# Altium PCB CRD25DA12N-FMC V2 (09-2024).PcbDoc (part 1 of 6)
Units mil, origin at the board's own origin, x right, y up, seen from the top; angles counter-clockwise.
Board outline 8000 x 8000 mil, 6 copper layers (Top Layer, Layer 2, Layer 3, Layer 4, Layer 5, Bottom Layer), stack 91 mil thick; 602 components, 333 nets, 1670 pads, 639 vias.
Unrouted connection lines stored in the file: 1.
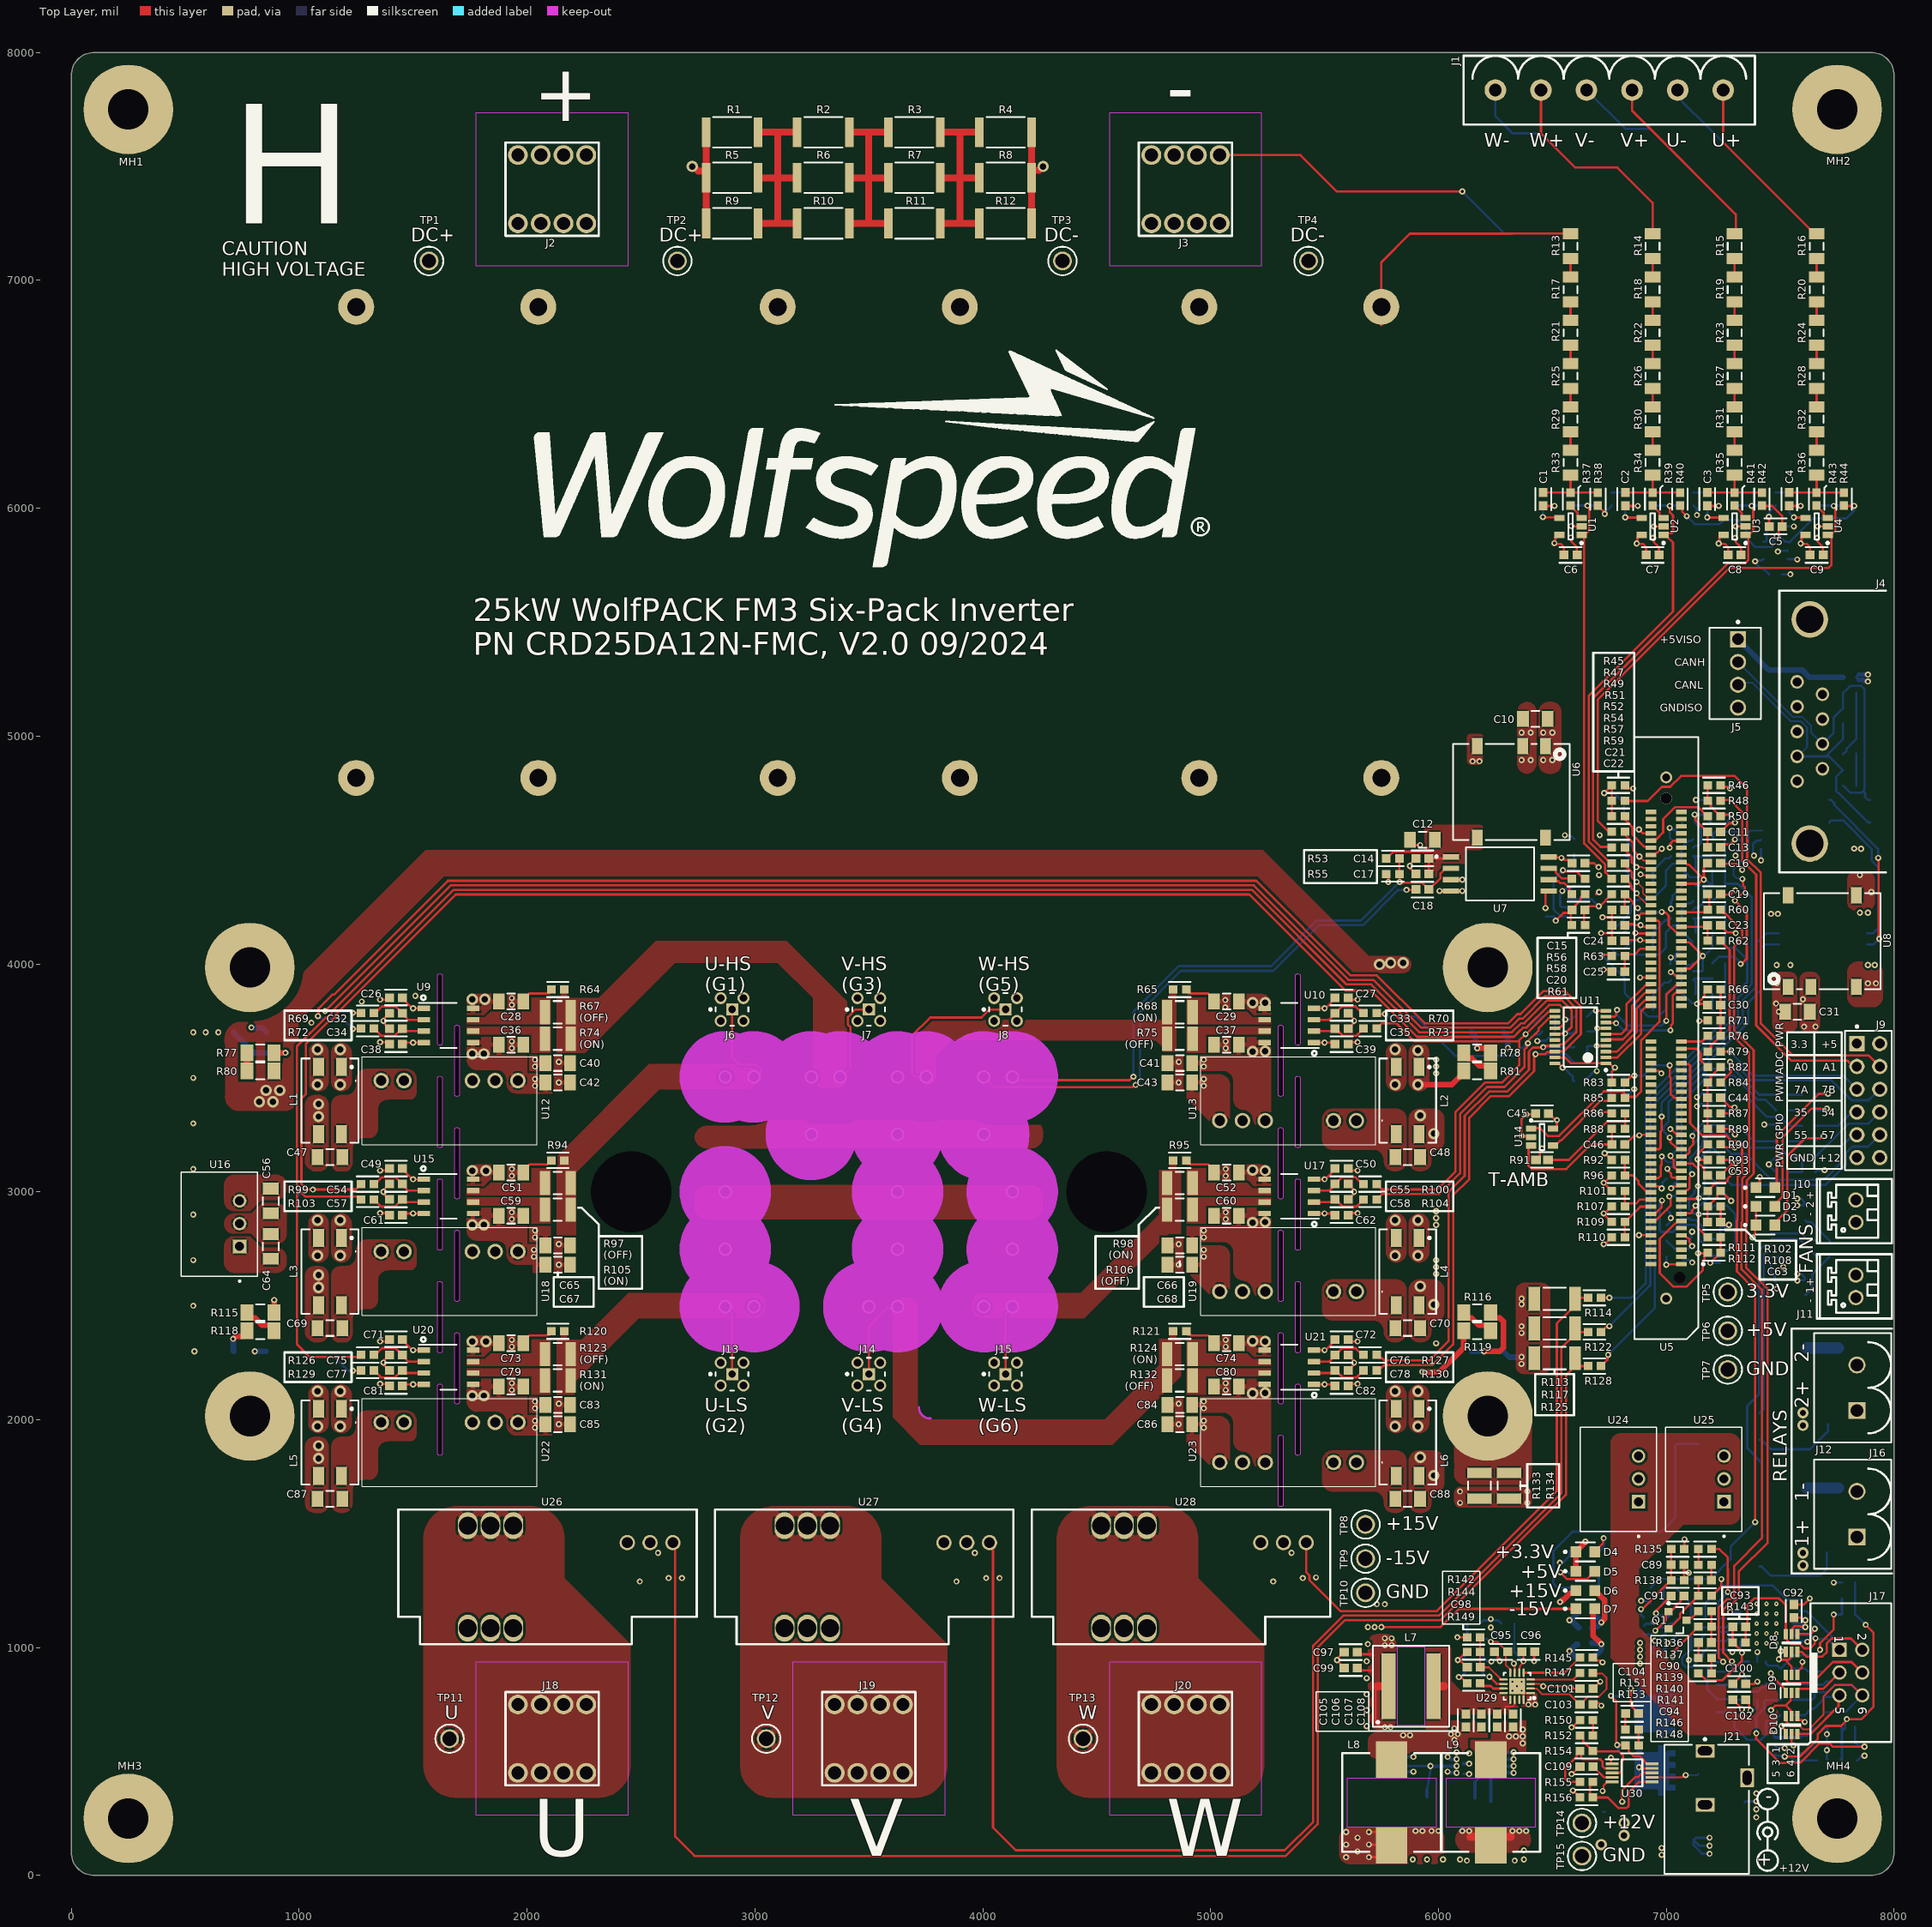
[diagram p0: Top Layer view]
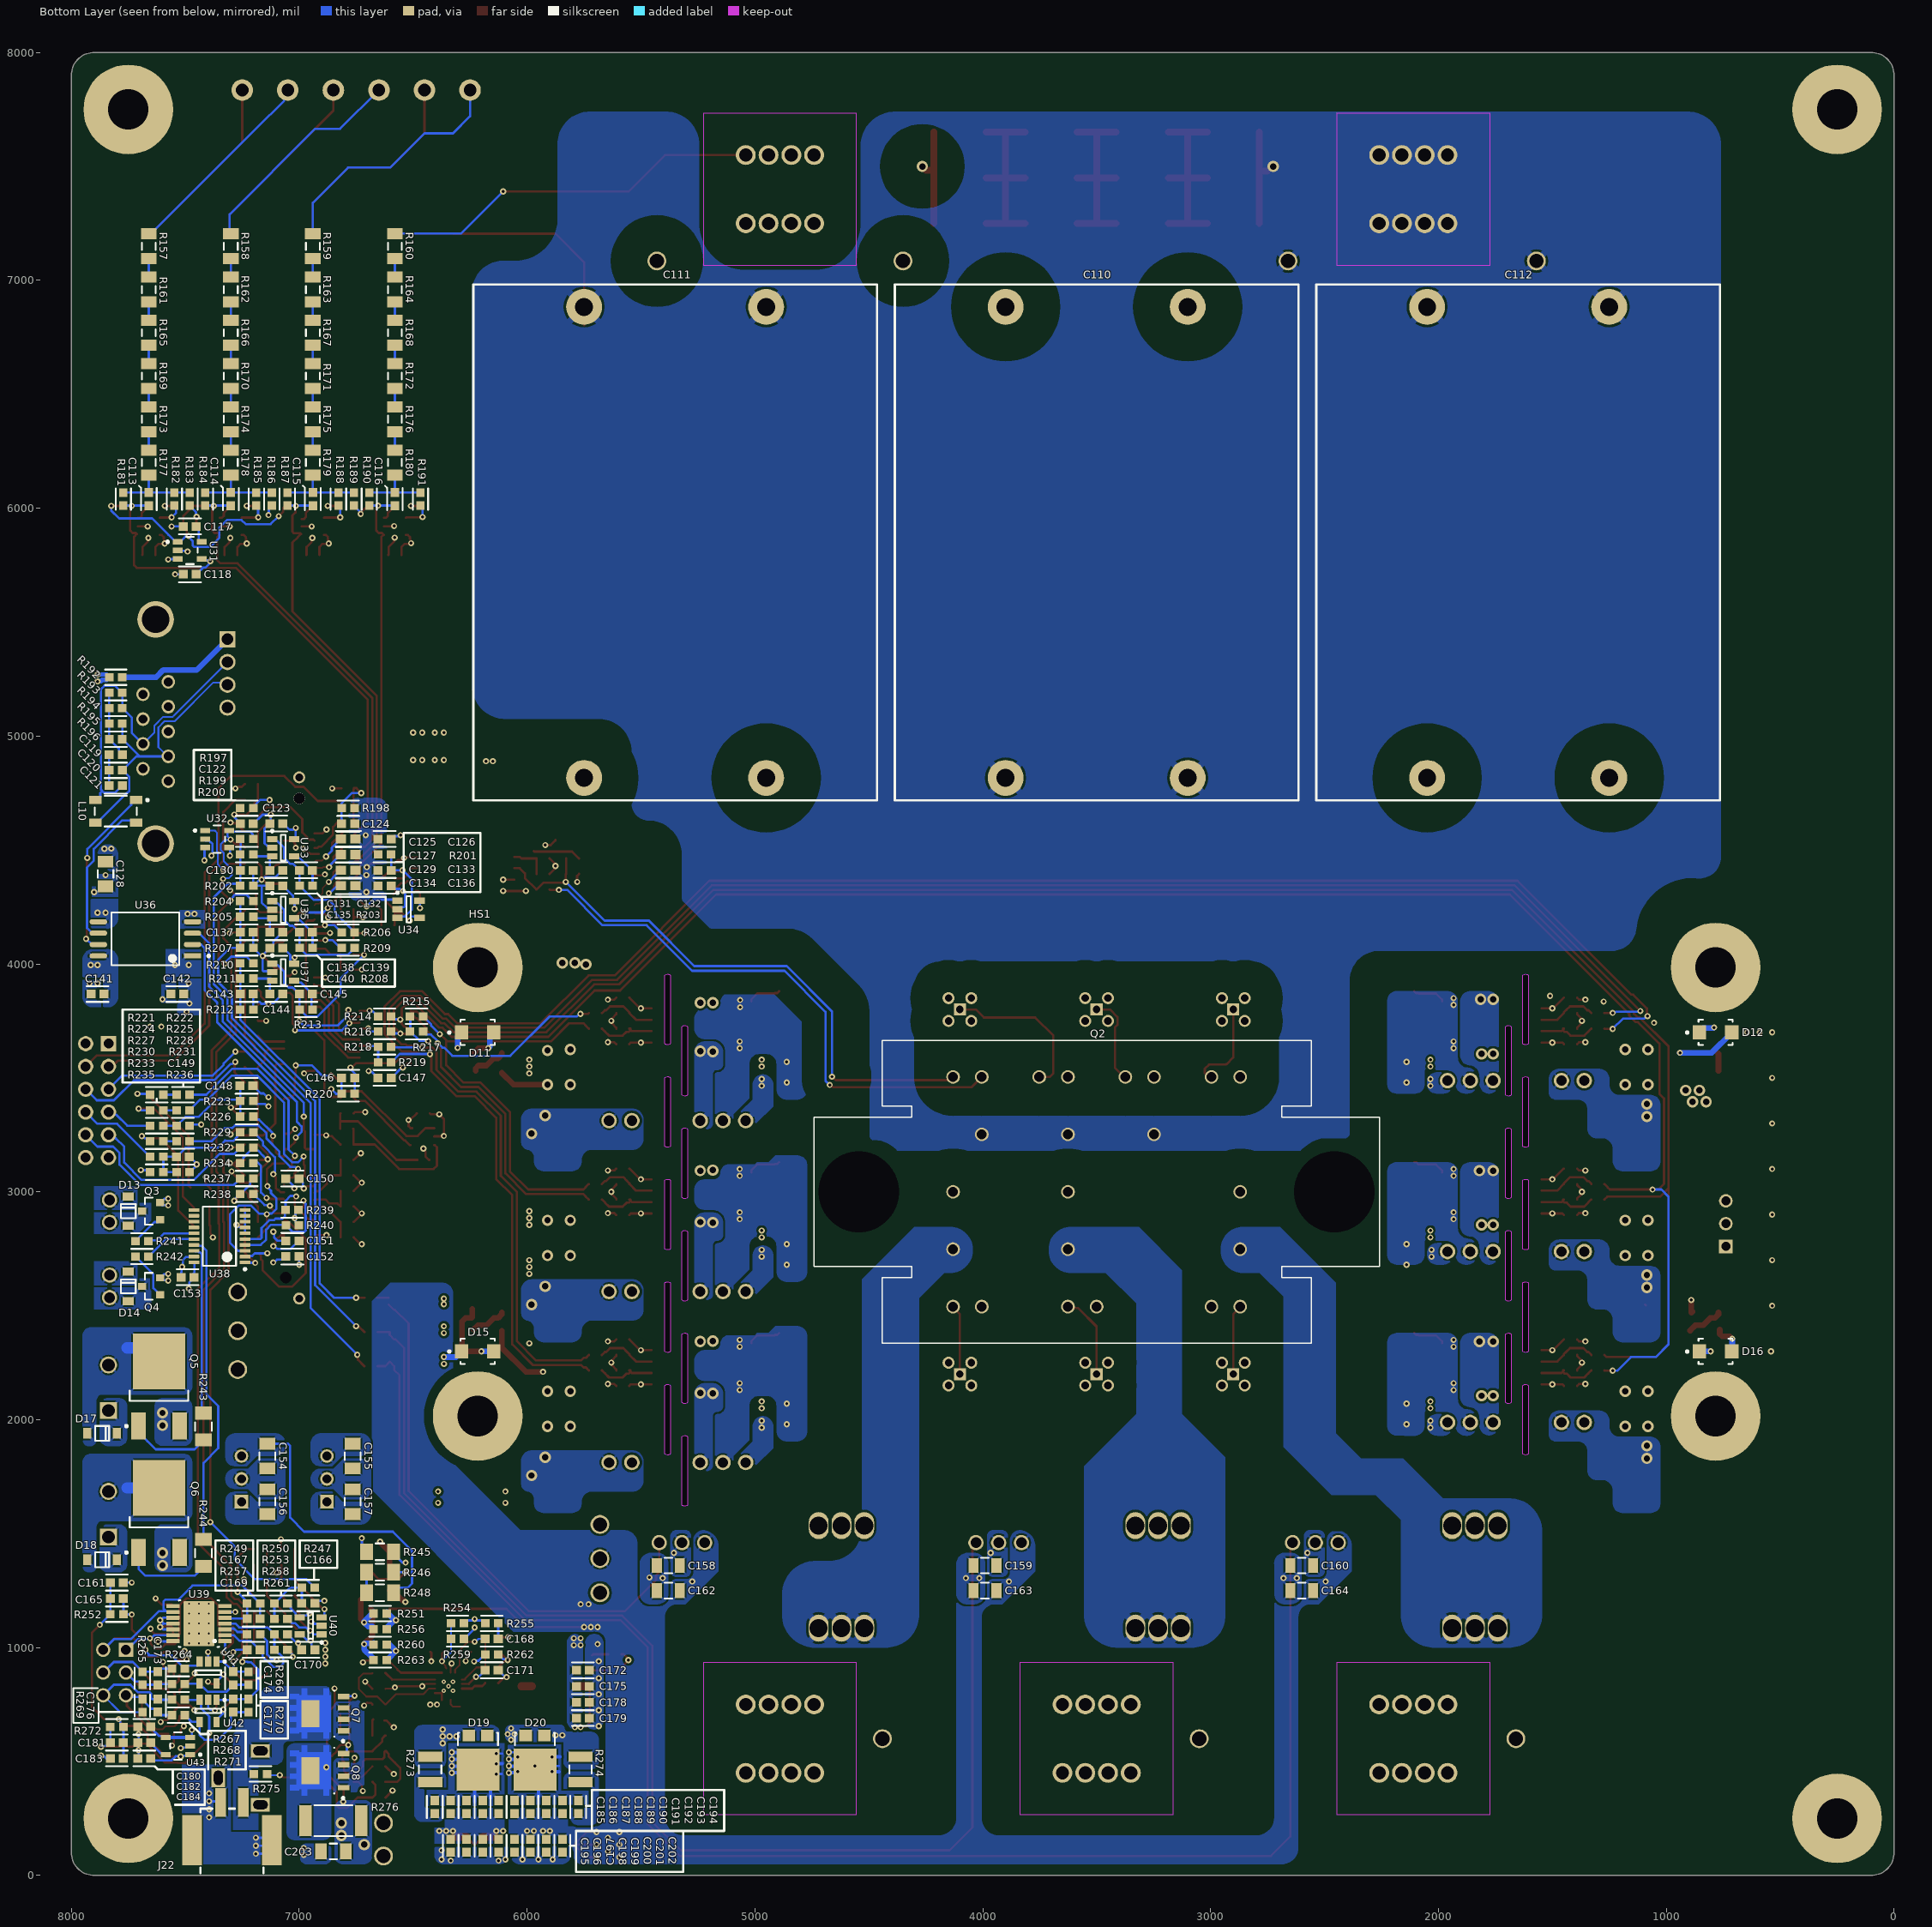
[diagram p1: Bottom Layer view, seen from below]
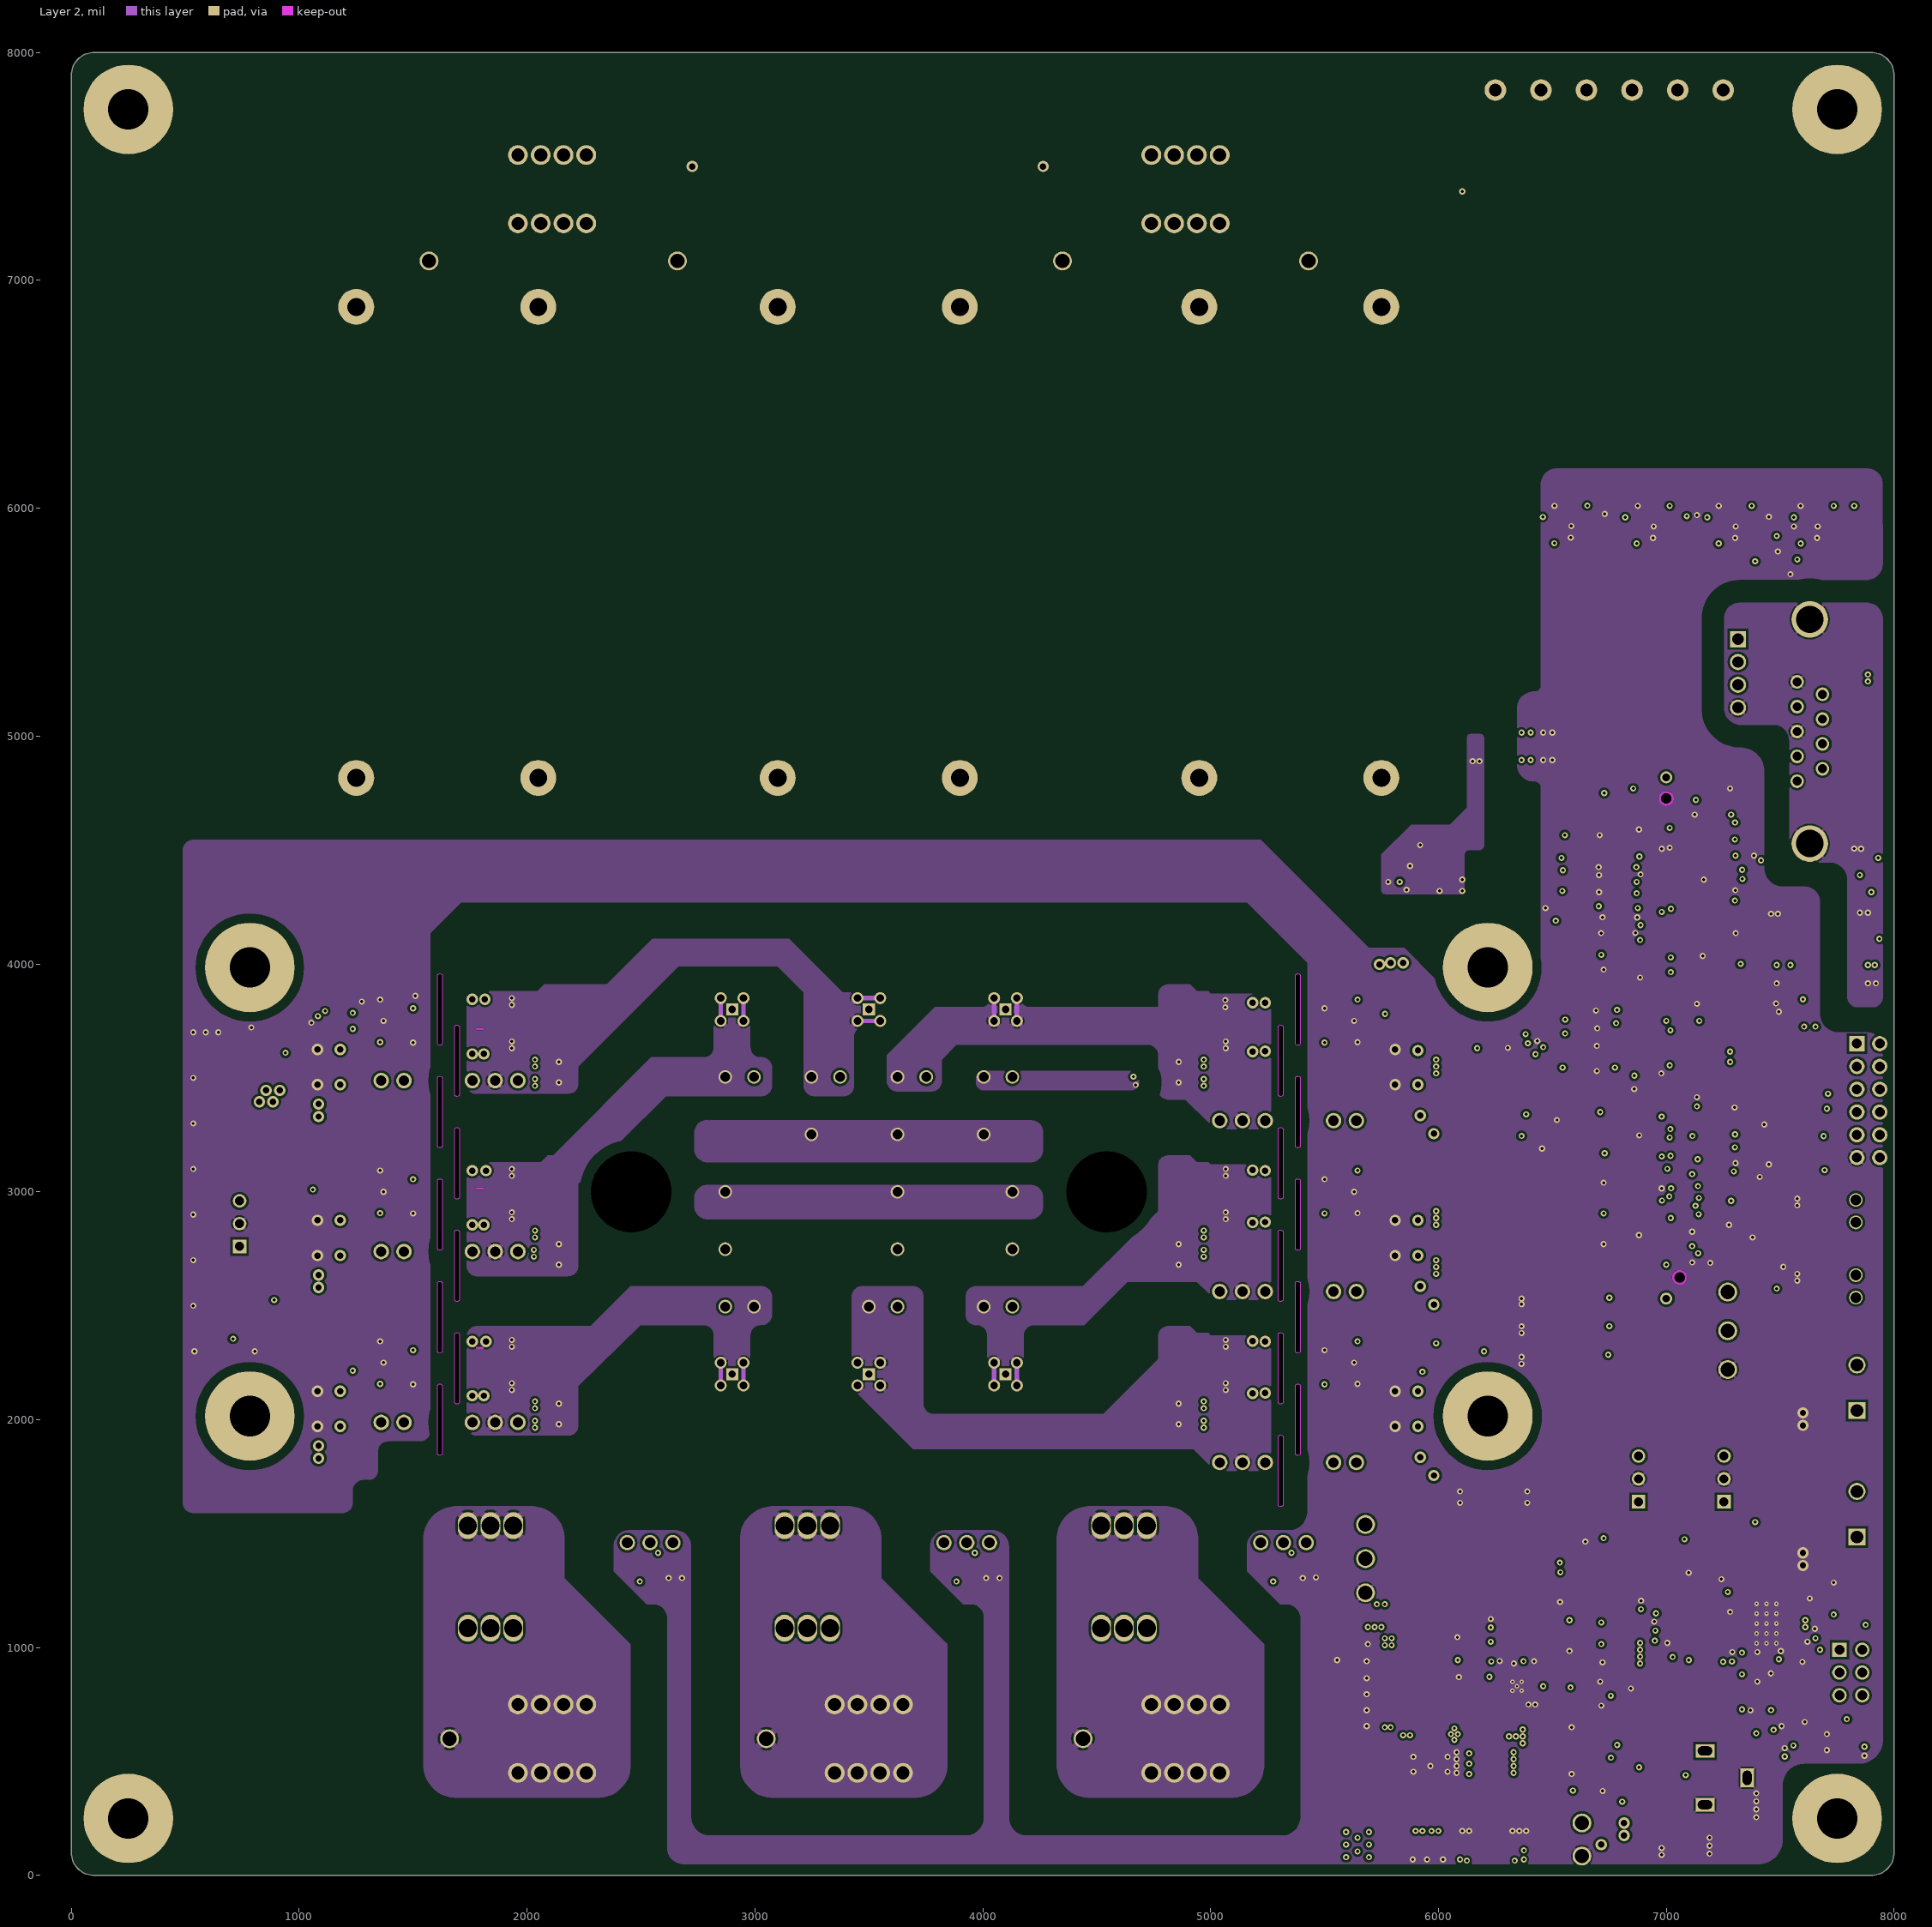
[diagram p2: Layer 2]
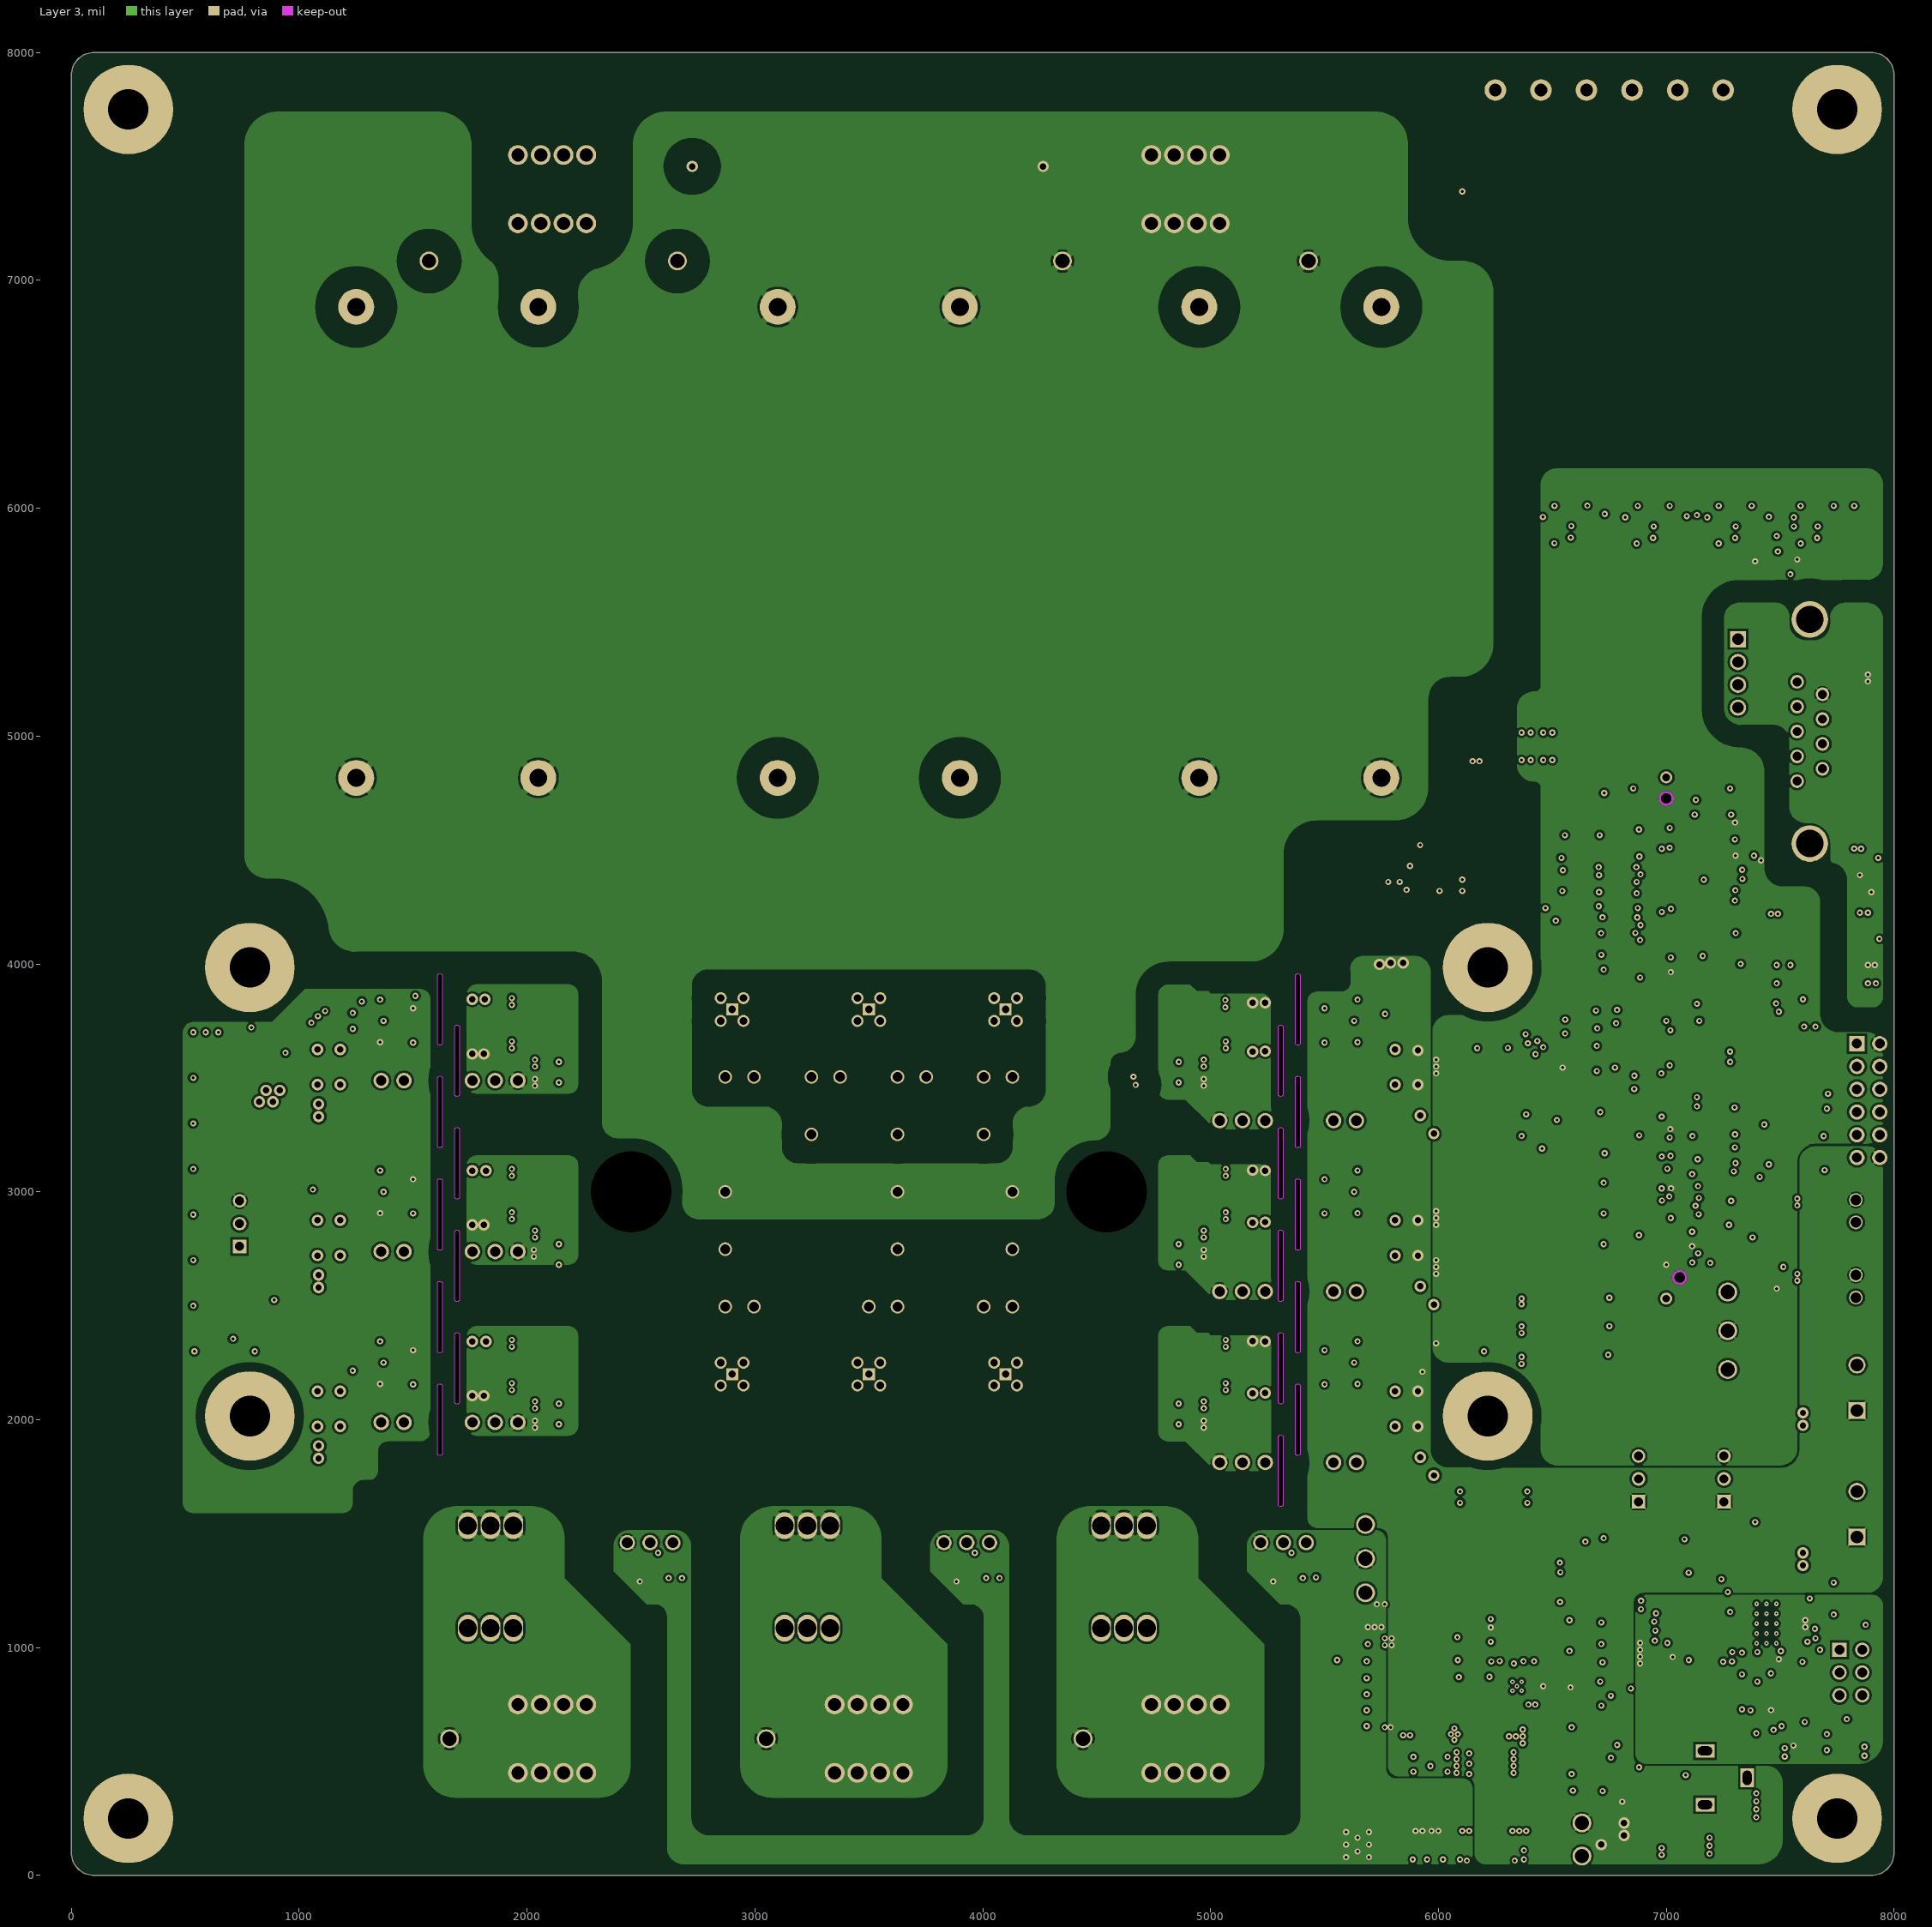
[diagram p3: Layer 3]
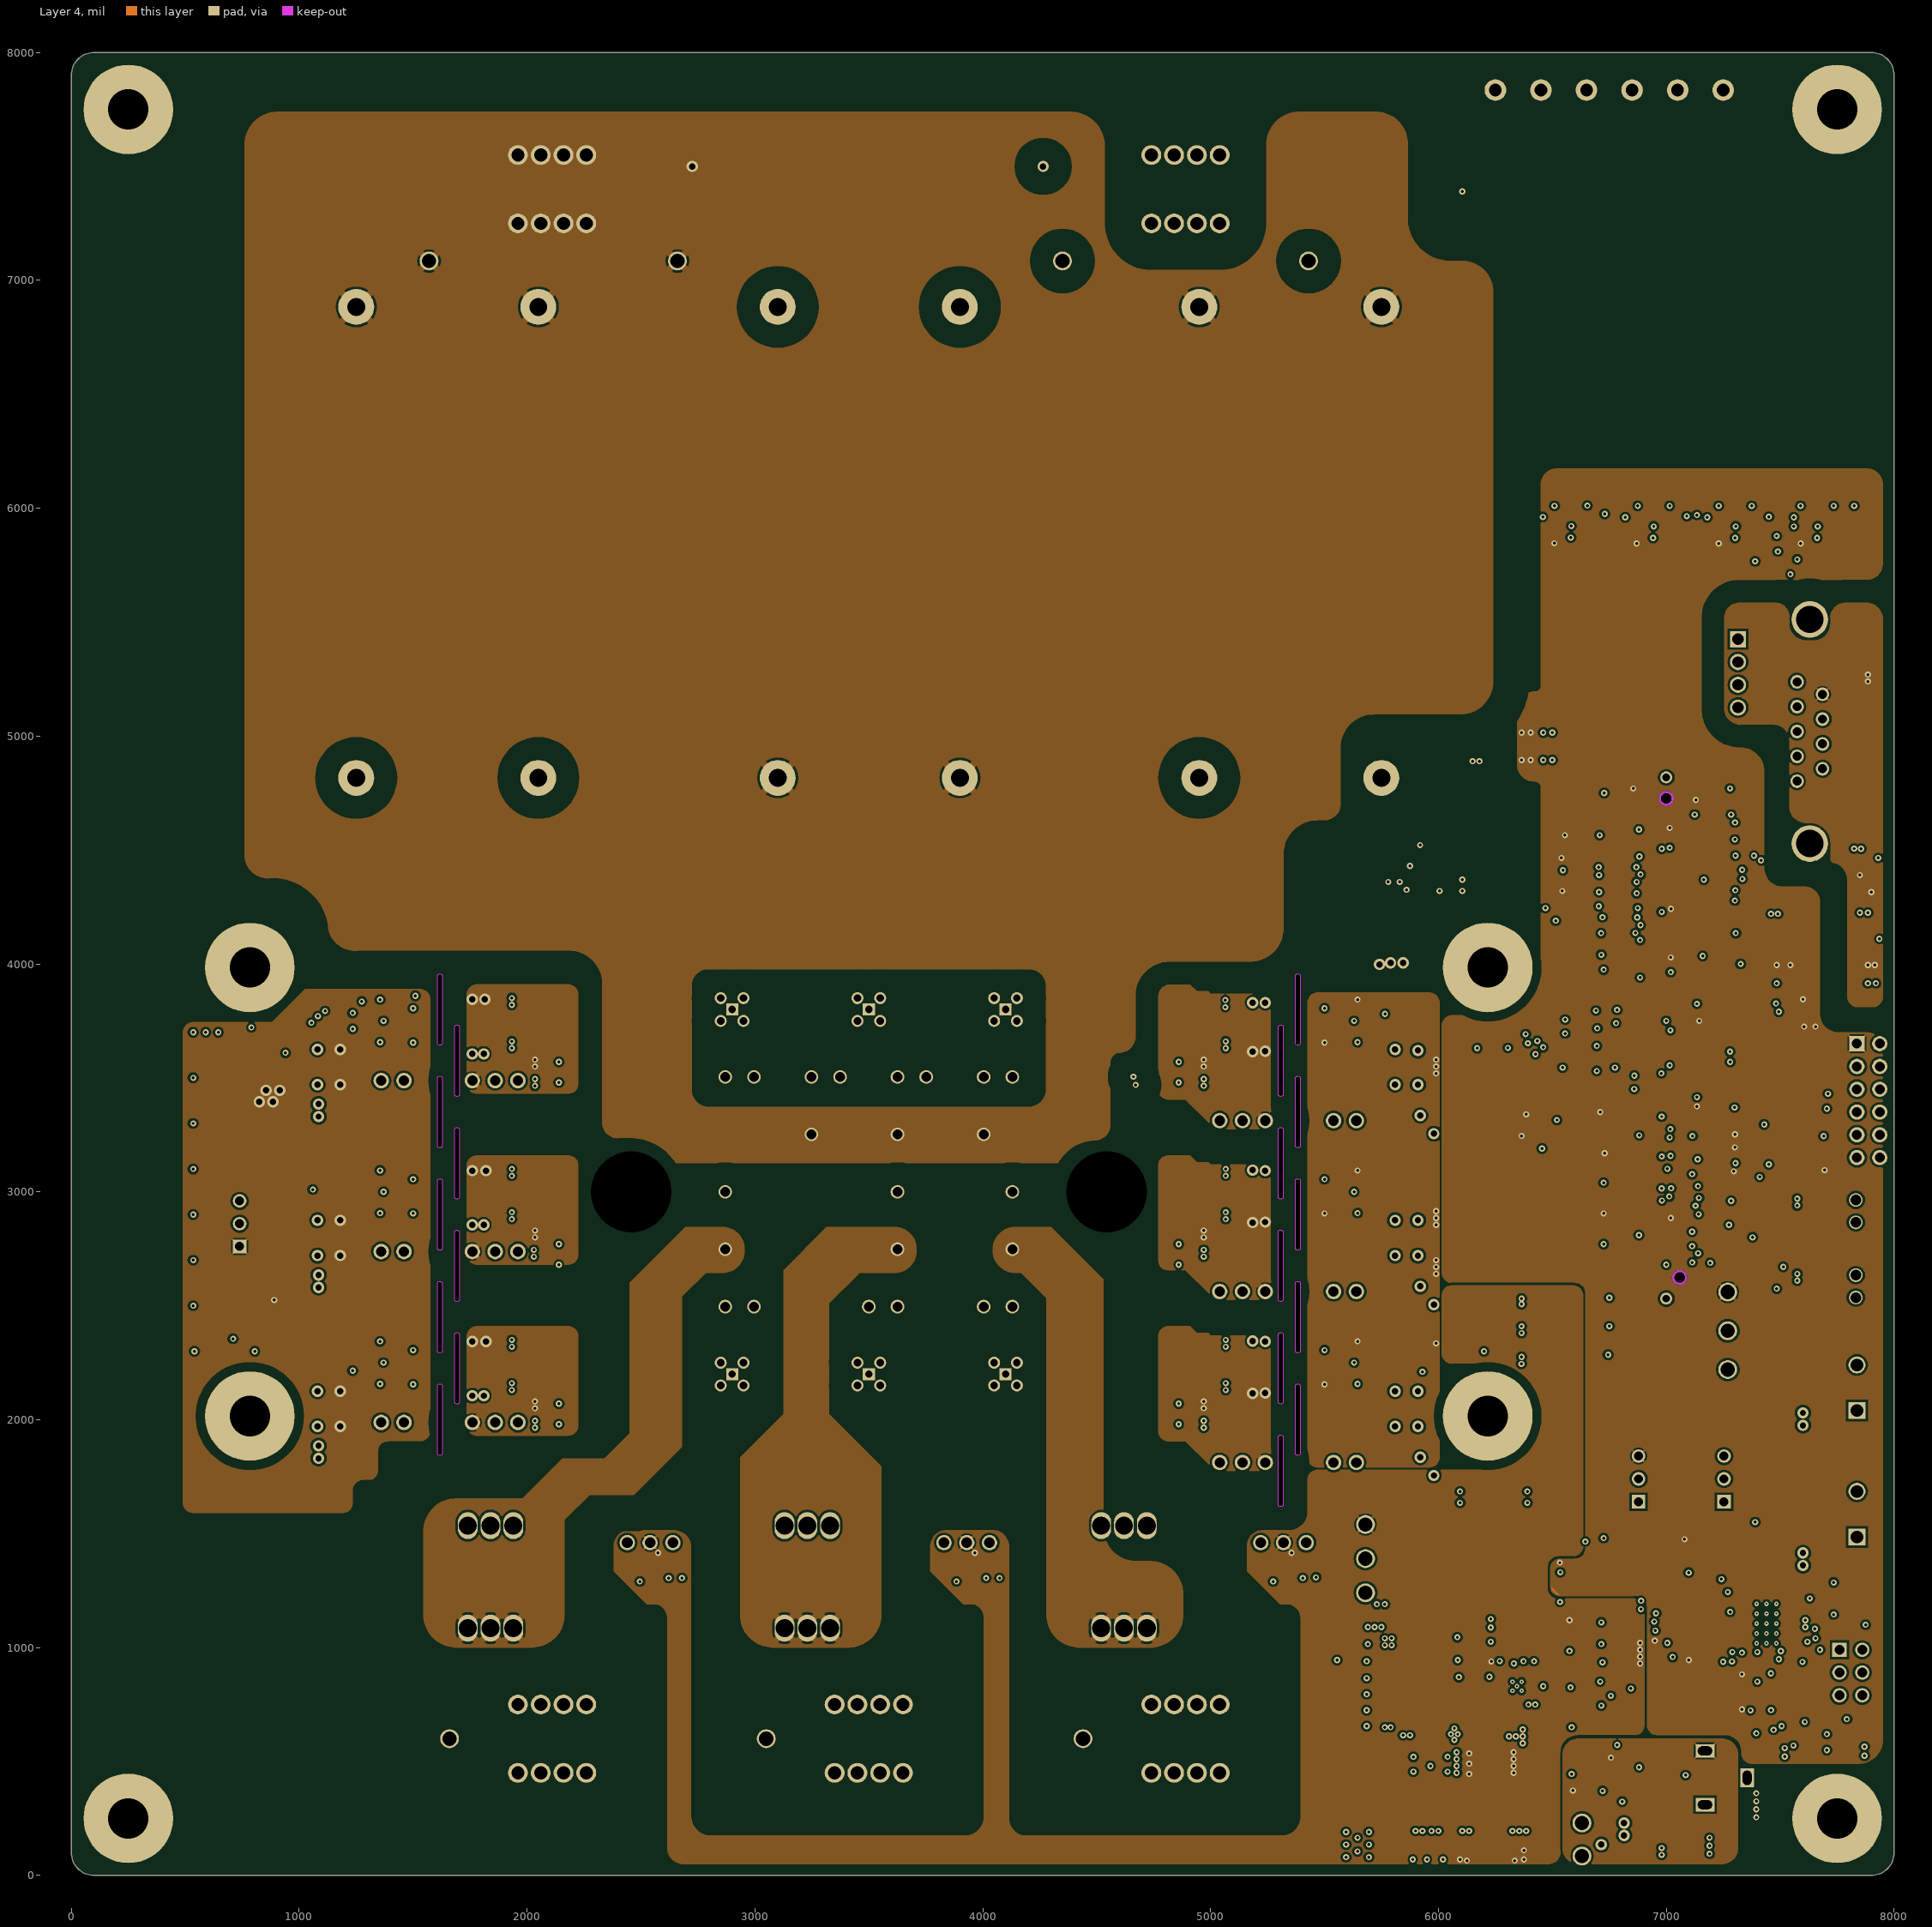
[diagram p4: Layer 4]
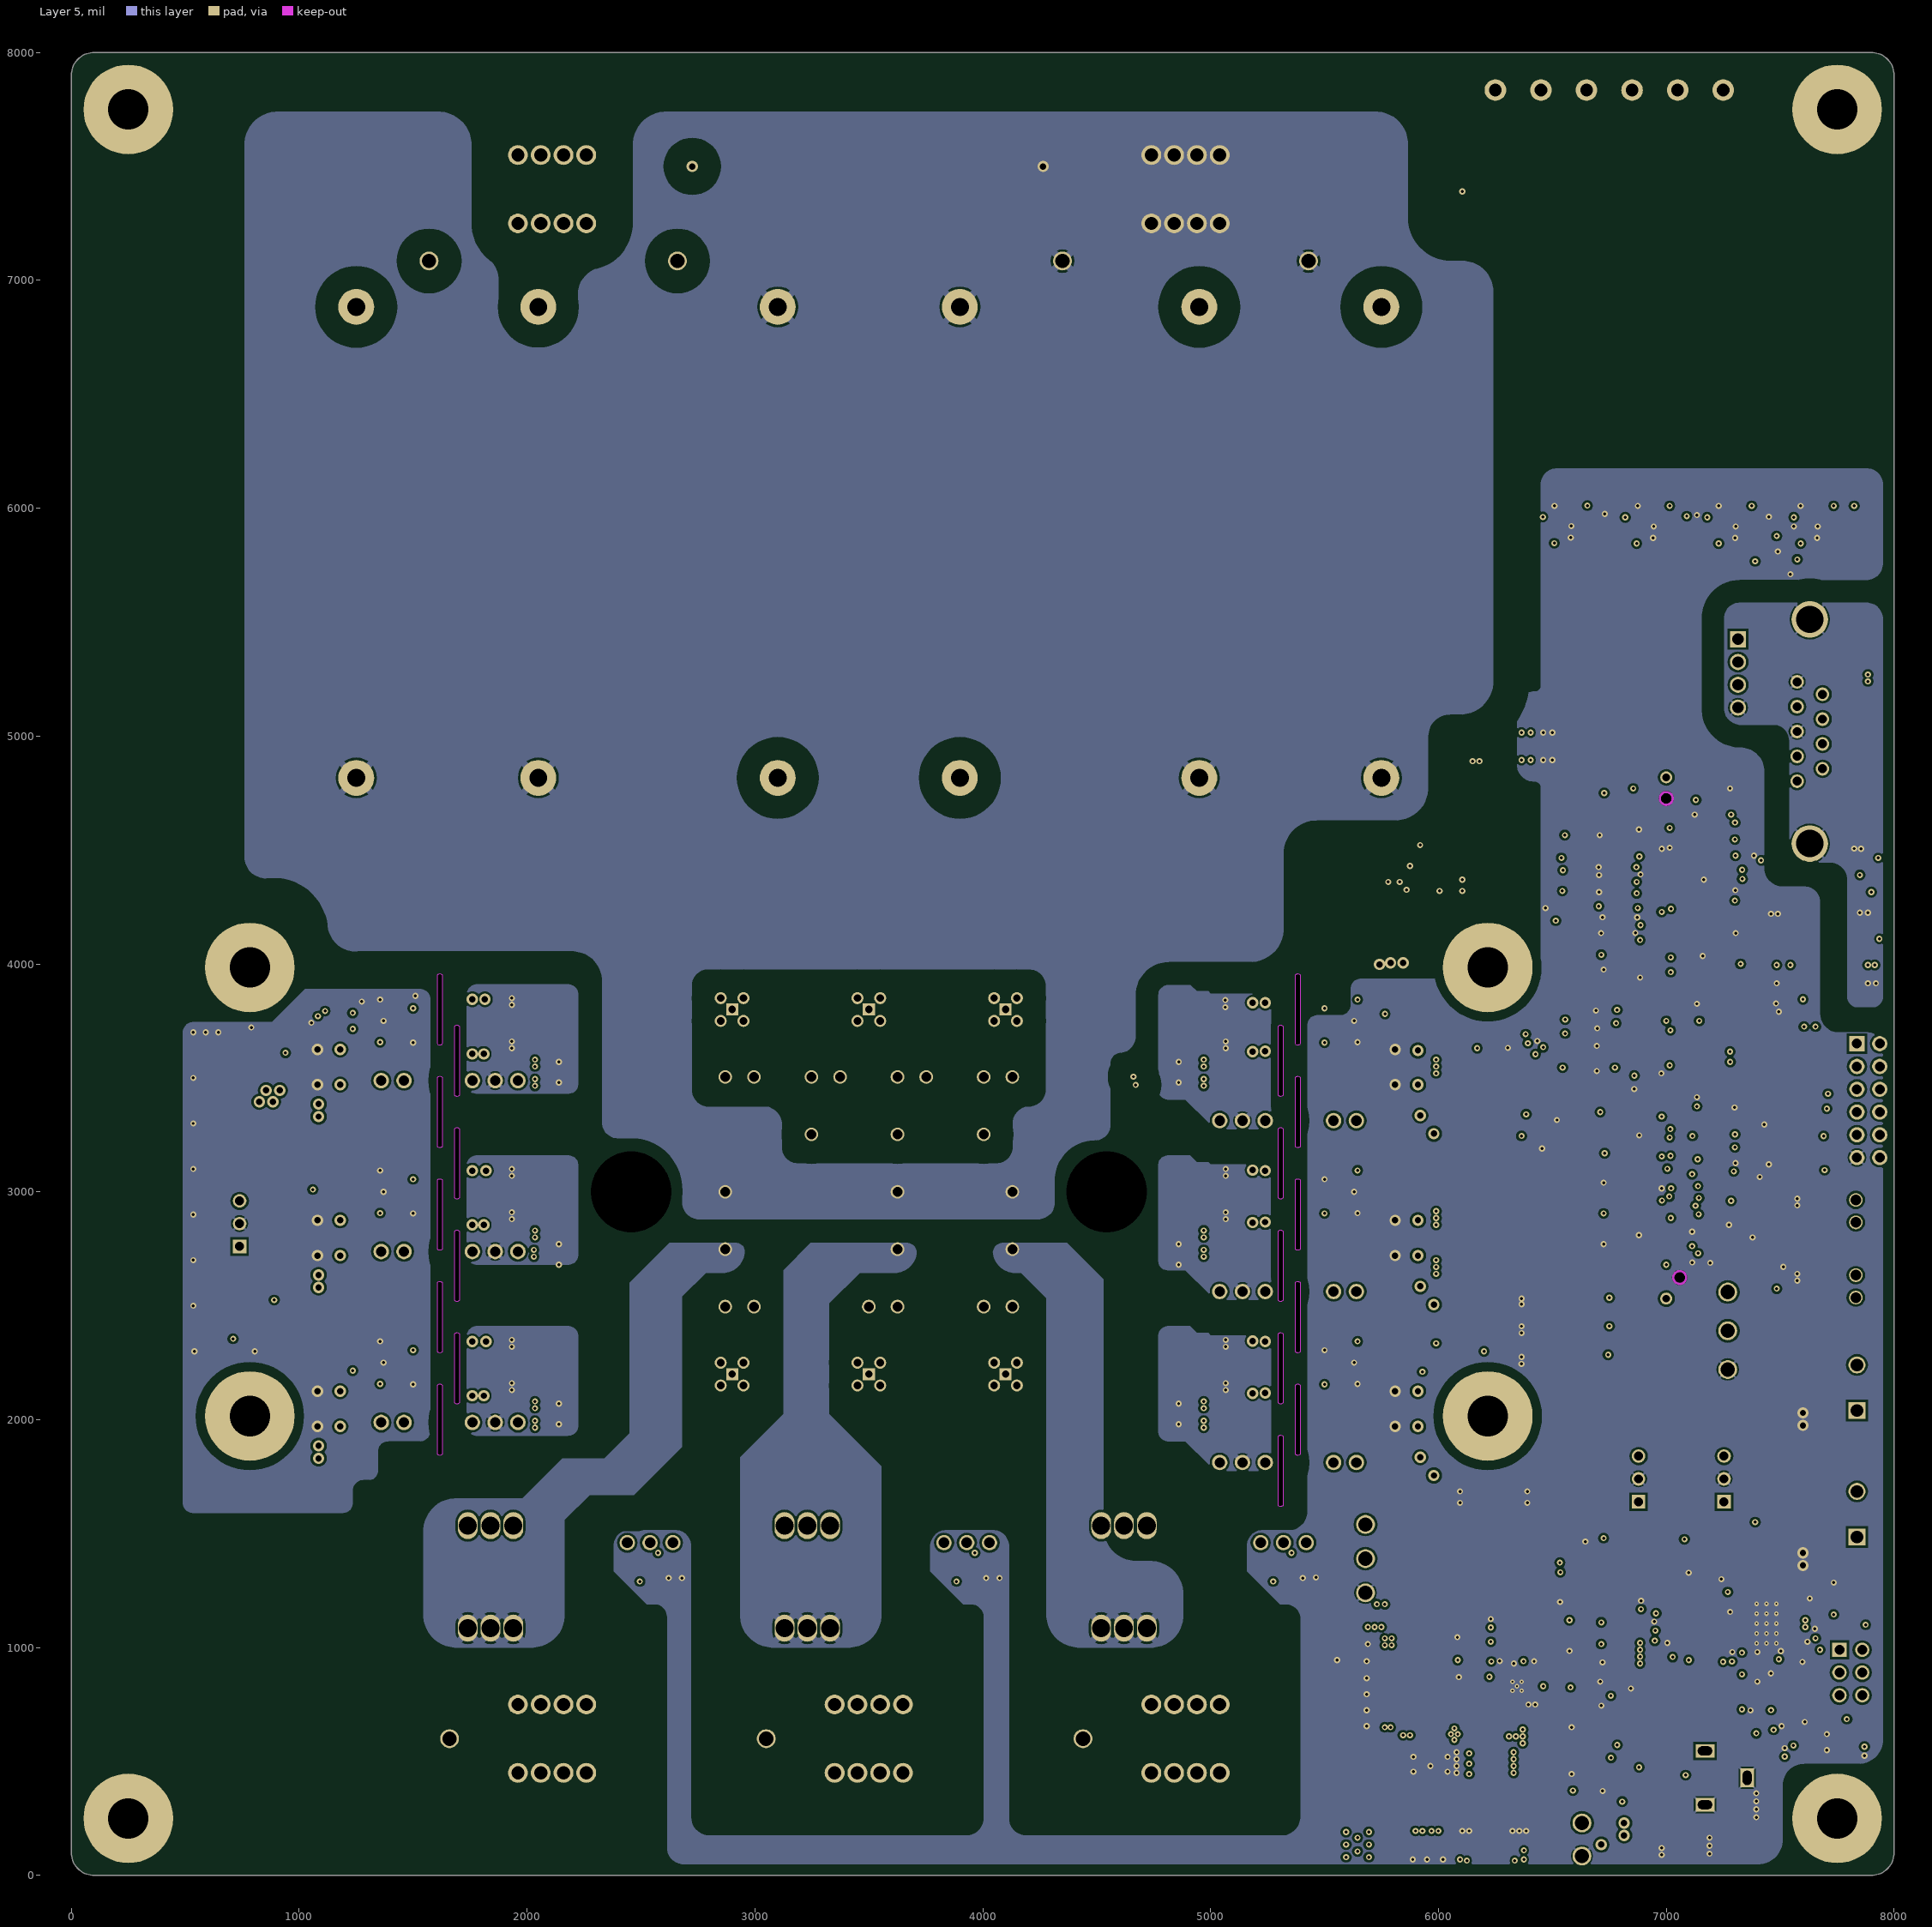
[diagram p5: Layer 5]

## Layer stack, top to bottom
Top Solder: solder mask 1, SM-002, Dk 4
Top Layer: signal copper 2.756
Dielectric 2: prepreg 7.894, PP-006, Dk 4.1
Layer 2: signal copper 2.756
Dielectric 4: prepreg 7.894, PP-006, Dk 4.1
Layer 3: signal copper 2.756
Dielectric 1: dielectric 42.888, FR-4, Dk 4.8
Layer 4: signal copper 2.756
Dielectric 5: prepreg 7.894, PP-006, Dk 4.1
Layer 5: signal copper 2.756
Dielectric 3: prepreg 7.894, PP-006, Dk 4.1
Bottom Layer: signal copper 2.756
Bottom Solder: solder mask 1, SM-002, Dk 4

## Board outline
0,100 0,7900 cw(c100,7900) 100,8000 7900,8000 cw(c7900,7900) 8000,7900 8000,100 cw(c7900,100) 7900,0 100,0 cw(c100,100)
cut-out: 5370,3950 5370,3650 ccw(c5382.5,3662.5) 5395,3650 5395,3950 ccw(c5382.5,3937.5)
cut-out: 5295,3725 5295,3425 ccw(c5307.5,3437.5) 5320,3425 5320,3725 ccw(c5307.5,3712.5)
cut-out: 5370,3500 5370,3200 ccw(c5382.5,3212.5) 5395,3200 5395,3500 ccw(c5382.5,3487.5)
cut-out: 5295,3275 5295,2975 ccw(c5307.5,2987.5) 5320,2975 5320,3275 ccw(c5307.5,3262.5)
cut-out: 5370,3050 5370,2750 ccw(c5382.5,2762.5) 5395,2750 5395,3050 ccw(c5382.5,3037.5)
cut-out: 5295,2825 5295,2525 ccw(c5307.5,2537.5) 5320,2525 5320,2825 ccw(c5307.5,2812.5)
cut-out: 5370,2600 5370,2300 ccw(c5382.5,2312.5) 5395,2300 5395,2600 ccw(c5382.5,2587.5)
cut-out: 5295,2375 5295,2075 ccw(c5307.5,2087.5) 5320,2075 5320,2375 ccw(c5307.5,2362.5)
cut-out: 5370,2150 5370,1850 ccw(c5382.5,1862.5) 5395,1850 5395,2150 ccw(c5382.5,2137.5)
cut-out: 5295,1925 5295,1625 ccw(c5307.5,1637.5) 5320,1625 5320,1925 ccw(c5307.5,1912.5)
cut-out: 1605,2150 1605,1850 ccw(c1617.5,1862.5) 1630,1850 1630,2150 ccw(c1617.5,2137.5)
cut-out: 1680,2375 1680,2075 ccw(c1692.5,2087.5) 1705,2075 1705,2375 ccw(c1692.5,2362.5)
cut-out: 1605,2600 1605,2300 ccw(c1617.5,2312.5) 1630,2300 1630,2600 ccw(c1617.5,2587.5)
cut-out: 1680,2825 1680,2525 ccw(c1692.5,2537.5) 1705,2525 1705,2825 ccw(c1692.5,2812.5)
cut-out: 1605,3050 1605,2750 ccw(c1617.5,2762.5) 1630,2750 1630,3050 ccw(c1617.5,3037.5)
cut-out: 1680,3275 1680,2975 ccw(c1692.5,2987.5) 1705,2975 1705,3275 ccw(c1692.5,3262.5)
cut-out: 1605,3500 1605,3200 ccw(c1617.5,3212.5) 1630,3200 1630,3500 ccw(c1617.5,3487.5)
cut-out: 1680,3725 1680,3425 ccw(c1692.5,3437.5) 1705,3425 1705,3725 ccw(c1692.5,3712.5)
cut-out: 1605,3950 1605,3650 ccw(c1617.5,3662.5) 1630,3650 1630,3950 ccw(c1617.5,3937.5)

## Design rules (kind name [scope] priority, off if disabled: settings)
Clearance Keepout [IsKeepOut] p1: gap=0 ignorepadtopadclearanceinfootprint=FALSE
Clearance DC+/-_Heatsink [InNet('DC-') Or InNet('DC+') vs HasFootprint('LA 6 150 12')] p2: gap=160 ignorepadtopadclearanceinfootprint=FALSE except(0: Arc-Hole Track-Hole SMDPad-Hole THPad-Hole Via-Hole Fill-Hole Poly-Hole Region-Hole Text-Hole)
Clearance NTC_Heatsink [InNetClass('NTC Class') vs HasFootprint('LA 6 150 12')] p3: gap=120 ignorepadtopadclearanceinfootprint=FALSE except(0: Arc-Hole Track-Hole SMDPad-Hole THPad-Hole Via-Hole Fill-Hole Poly-Hole Region-Hole Text-Hole)
Clearance Heatsink [All vs HasFootprint('LA 6 150 12')] p4: gap=40 ignorepadtopadclearanceinfootprint=FALSE except(0: Arc-Hole Track-Hole SMDPad-Hole THPad-Hole Via-Hole Fill-Hole Poly-Hole Region-Hole Text-Hole)
Clearance Module_Mount [All vs HoleDiameter = 354.331] p5: gap=50 ignorepadtopadclearanceinfootprint=FALSE
Clearance Cutout [IsBoardCutoutRegion] p6: gap=20 ignorepadtopadclearanceinfootprint=TRUE except(0: Arc-Hole Track-Hole SMDPad-Hole THPad-Hole Via-Hole Fill-Hole Poly-Hole Region-Hole Text-Hole)
Clearance LV_to_G [InNetClass('LV Pours') vs InNetClass('Gate Class')] p7: gap=160 ignorepadtopadclearanceinfootprint=FALSE except(0: Arc-Hole Track-Hole SMDPad-Hole THPad-Hole Via-Hole Fill-Hole Poly-Hole Region-Hole Text-Hole)
Clearance DC+/-_to_LV [InNet('DC-') OR InNet('DC+') OR InNetClass('U Class') OR InNetClass('V Class') OR InNetClass('W Class') vs InNetClass('LV Pours')] p8: gap=160 ignorepadtopadclearanceinfootprint=FALSE except(0: Arc-Hole Track-Hole SMDPad-Hole THPad-Hole Via-Hole Fill-Hole Poly-Hole Region-Hole Text-Hole)
Clearance DC+_Internal [(InNet('DC-') Or InNetClass('DC+ Class')) AND InLayerClass('Internal Layers')] p9: gap=100 ignorepadtopadclearanceinfootprint=FALSE except(0: Arc-Hole Track-Hole SMDPad-Hole THPad-Hole Via-Hole Fill-Hole Poly-Hole Region-Hole Text-Hole)
Clearance DC+_Pins_External [InNet('DC+') AND InLayerClass('External Layers') vs (HasFootprint('FM3_SIX-PACK_3PHASE_CRW') OR HasFootprint('FP-73415-1471-MFG')) AND (InNetClass('Gate Class') OR InNetClass('NTC Class'))] p10: gap=140 ignorepadtopadclearanceinfootprint=FALSE except(0: Arc-Hole Track-Hole SMDPad-Hole THPad-Hole Via-Hole Fill-Hole Poly-Hole Region-Hole Text-Hole)
Clearance DC+_to_DC+ [InNetClass('DC+ Class') vs InNetClass('DC+ Class')] p11: gap=10 ignorepadtopadclearanceinfootprint=FALSE except(0: Arc-Hole Track-Hole SMDPad-Hole THPad-Hole Via-Hole Fill-Hole Poly-Hole Region-Hole Text-Hole)
Clearance DC+_External [InNet('DC+') AND InLayerClass('External Layers')] p12: gap=160 ignorepadtopadclearanceinfootprint=FALSE except(0: Arc-Text Arc-Hole Track-Text Track-Hole SMDPad-Text SMDPad-Hole THPad-Text THPad-Hole Via-Text Via-Hole Fill-Text Fill-Hole Poly-Text Poly-Hole Region-Text Region-Hole Text-Text Text-Hole)
Clearance CAN [InNetClass('CAN Class') vs Not InNetClass('CAN Class') And Not IsPad] p13: gap=100 ignorepadtopadclearanceinfootprint=FALSE except(0: Arc-Hole Track-Hole SMDPad-Hole THPad-Hole Via-Hole Fill-Hole Poly-Hole Region-Hole Text-Hole)
Clearance U [InNetClass('U Class') vs NOT InNetClass('U Class')] p14: gap=100 ignorepadtopadclearanceinfootprint=FALSE except(0: Arc-Text Arc-Hole Track-Text Track-Hole SMDPad-Text SMDPad-Hole THPad-Text THPad-Hole Via-Text Via-Hole Fill-Text Fill-Hole Poly-Text Poly-Hole Region-Text Region-Hole Text-Text Text-Hole)
Clearance V [InNetClass('V Class') vs NOT InNetClass('V Class')] p15: gap=100 ignorepadtopadclearanceinfootprint=FALSE except(0: Arc-Text Arc-Hole Track-Text Track-Hole SMDPad-Text SMDPad-Hole THPad-Text THPad-Hole Via-Text Via-Hole Fill-Text Fill-Hole Poly-Text Poly-Hole Region-Text Region-Hole Text-Text Text-Hole)
Clearance W [InNetClass('W Class') vs NOT InNetClass('W Class')] p16: gap=100 ignorepadtopadclearanceinfootprint=FALSE except(0: Arc-Hole Track-Hole SMDPad-Hole THPad-Hole Via-Hole Fill-Hole Poly-Hole Region-Hole Text-Text Text-Hole)
Clearance NTC_External [InNetClass('NTC Class') AND InLayerClass('External Layers') vs NOT InNetClass('NTC Class') AND NOT IsPad] p17: gap=150 ignorepadtopadclearanceinfootprint=FALSE except(0: Arc-Hole Track-Hole SMDPad-Hole THPad-Hole Via-Hole Fill-Hole Poly-Hole Region-Hole Text-Hole)
Clearance NTC_Internal [InNetClass('NTC Class') AND InLayerClass('Internal Layers') vs NOT InNetClass('NTC Class') AND NOT IsPad] p18: gap=100 ignorepadtopadclearanceinfootprint=FALSE except(0: Arc-Hole Track-Hole SMDPad-Hole THPad-Hole Via-Hole Fill-Hole Poly-Hole Region-Hole Text-Hole)
Clearance [All] p19: gap=10 ignorepadtopadclearanceinfootprint=TRUE except(0: Arc-Hole Track-Hole SMDPad-Hole THPad-Hole Via-Hole Fill-Poly Fill-Hole Poly-Hole Region-Hole Text-Hole; 6: Arc-SMDPad Track-SMDPad SMDPad-SMDPad THPad-THPad)
Height [All] p1: minheight=0 maxheight=4100 prefheight=500
HoleSize [All] p1: absolutevalues=TRUE maxlimit=400 minlimit=5 maxpercent=80.000 minpercent=20.000
MinimumSolderMaskSliver [All] p1: minsoldermaskwidth=1.5
PolygonConnect InductorConnect [HasFootprint('74437368220')] p1: connectstyle=Direct reliefconductorwidth=10 reliefentries=4 polygonreliefangle="90 Angle" airgapwidth=10
PolygonConnect BoltConnect [HoleDiameter=177.165] p2: thpad.connectstyle=Direct thpad.reliefconductorwidth=10 thpad.reliefentries=4 thpad.polygonreliefangle="90 Angle" thpad.airgapwidth=10 smdpad.connectstyle=Relief smdpad.reliefconductorwidth=10 smdpad.reliefentries=4 smdpad.polygonreliefangle="90 Angle" smdpad.airgapwidth=10 via.connectstyle=Relief via.reliefconductorwidth=10 via.reliefentries=4 via.polygonreliefangle="90 Angle" via.airgapwidth=10
PolygonConnect PressFitConnect [HasFootprint('7460307')] p3: connectstyle=Direct reliefconductorwidth=10 reliefentries=4 polygonreliefangle="90 Angle" airgapwidth=10
PolygonConnect ModuleConnect [HasFootprint('FM3_SIX-PACK_3PHASE_CRW')] p4: connectstyle=Direct reliefconductorwidth=30 reliefentries=4 polygonreliefangle="45 Angle" airgapwidth=10
PolygonConnect PourOverThruConnect [InNetClass('Pour-Over Thru Class') AND NOT HasFootprint('FM3_SIX-PACK_3PHASE_CRW')] p5: thpad.connectstyle=Relief thpad.reliefconductorwidth=20 thpad.reliefentries=4 thpad.polygonreliefangle="45 Angle" thpad.airgapwidth=7 smdpad.connectstyle=Relief smdpad.reliefconductorwidth=20 smdpad.reliefentries=4 smdpad.polygonreliefangle="90 Angle" smdpad.airgapwidth=8 via.connectstyle=Direct via.reliefconductorwidth=10 via.reliefentries=4 via.polygonreliefangle="90 Angle" via.airgapwidth=10
PolygonConnect PourOverConnect [InNetClass('Pour-Over Class')] p6: connectstyle=Direct reliefconductorwidth=10 reliefentries=4 polygonreliefangle="90 Angle" airgapwidth=10
PolygonConnect ViaConnect [IsVia] p7: connectstyle=Direct reliefconductorwidth=10 reliefentries=4 polygonreliefangle="90 Angle" airgapwidth=10
PolygonConnect HighCurrentThermalConnect [InNetClass('High-Current Class') AND NOT HasFootprint('FM3_SIX-PACK_3PHASE_CRW')] p8: thpad.connectstyle=Relief thpad.reliefconductorwidth=30 thpad.reliefentries=4 thpad.polygonreliefangle="45 Angle" thpad.airgapwidth=10 smdpad.connectstyle=Relief smdpad.reliefconductorwidth=10 smdpad.reliefentries=4 smdpad.polygonreliefangle="45 Angle" smdpad.airgapwidth=10 via.connectstyle=Direct via.reliefconductorwidth=10 via.reliefentries=4 via.polygonreliefangle="90 Angle" via.airgapwidth=10
PolygonConnect [All] p9: connectstyle=Relief reliefconductorwidth=10 reliefentries=4 polygonreliefangle="45 Angle" airgapwidth=7
RoutingVias [All] p1: holewidth=28 width=50 viastyle="Through Hole" minholewidth=28 minwidth=50 maxholewidth=28 maxwidth=50
SilkToSilkClearance [All] p1: silktosilkclearance=4
SilkToSolderMaskClearance [IsPad] p1: minsilkscreentomaskgap=2 clearancetoexposedcopper=TRUE
SolderMaskExpansion [All] p1: expansion=4 istentingtop=FALSE
SupplyNets "Schematic Supply Nets_17" [InNet('VIN')] p1: voltage=0.000
SupplyNets "Schematic Supply Nets_16" [InNet('GND_NTC')] p2: voltage=0.000
SupplyNets "Schematic Supply Nets_15" [InNet('GND_ISO')] p3: voltage=0.000
SupplyNets "Schematic Supply Nets_14" [InNet('+3.3V_I')] p4: voltage=0.000
SupplyNets "Schematic Supply Nets_13" [InNet('+5V')] p5: voltage=0.000
SupplyNets "Schematic Supply Nets_12" [InNet('+3.3V')] p6: voltage=0.000
SupplyNets "Schematic Supply Nets_11" [InNet('+5V_ISO')] p7: voltage=0.000
SupplyNets "Schematic Supply Nets_10" [InNet('GND')] p8: voltage=0.000
SupplyNets "Schematic Supply Nets_9" [InNet('+1.65V_V')] p9: voltage=0.000
SupplyNets "Schematic Supply Nets_8" [InNet('-15V')] p10: voltage=0.000
SupplyNets "Schematic Supply Nets_7" [InNet('+12V')] p11: voltage=0.000
SupplyNets "Schematic Supply Nets_6" [InNet('+5V_NTC')] p12: voltage=0.000
SupplyNets "Schematic Supply Nets_5" [InNet('+1.65V_I')] p13: voltage=0.000
SupplyNets "Schematic Supply Nets_4" [InNet('+3.3V_V')] p14: voltage=0.000
SupplyNets "Schematic Supply Nets_3" [InNet('+3.3V_R')] p15: voltage=0.000
SupplyNets "Schematic Supply Nets_2" [InNet('+15V')] p16: voltage=0.000
SupplyNets "Schematic Supply Nets_1" [InNet('+1.65V_R')] p17: voltage=0.000
SupplyNets "Schematic Supply Nets" [InNet('+5V_ALT')] p18: voltage=0.000
Width [All] p1: maxlimit=100 minlimit=6.5 preferedwidth=10 minimp=50.000000 maximp=50.000000 favimp=50.000000
25 further rules are at their usual default settings.

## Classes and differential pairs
component class "09 - Controlled Power": D13 D14 D17 D18 J10 J11 J12 J16 Q3 Q4 Q5 Q6 R241 R242 R243 R244
net class "Gate Class": +15V_U_HS +15V_U_LS +15V_V_HS +15V_V_LS +15V_W_HS +15V_W_LS -3V_U_HS -3V_U_LS -3V_V_HS -3V_V_LS -3V_W_HS -3V_W_LS G1 G1H G1L G2 G2H G2L G3 G3H G3L G4 G4H G4L G5 G5H G5L G6 G6H G6L S1 S2 S3 S4 S5 S6
net class "LV Pours": +3.3V +5V +5V_ALT +12V +15V -15V GND
net class "DC+ Class": DC+ DC+1
net class "G6 Class": +15V_W_LS -3V_W_LS G6 G6H G6L S6
net class "G5 Class": +15V_W_HS -3V_W_HS G5 G5H G5L S5
net class "G4 Class": +15V_V_LS -3V_V_LS G4 G4H G4L S4
net class "G3 Class": +15V_V_HS -3V_V_HS G3 G3H G3L S3
net class "G2 Class": +15V_U_LS -3V_U_LS G2 G2H G2L S2
net class "G1 Class": +15V_U_HS -3V_U_HS G1 G1H G1L S1
net class "CAN Class": +5V_ISO +5V_ISO_BUF CAN_H CAN_HFILT CAN_L CAN_LFILT CAN_MIDC CAN_MIDR GND_ISO
net class "NTC Class": +5V_NTC GND_NTC NTC1
net class "Pour-Over Thru Class": +15V_U_HS +15V_U_LS +15V_V_HS +15V_V_LS +15V_W_HS +15V_W_LS -3V_U_HS -3V_U_LS -3V_V_HS -3V_V_LS -3V_W_HS -3V_W_LS S1 S2 S3 S4 S5 S6
net class "Pour-Over Class": G1 G1H G1L G2 G2H G2L G3 G3H G3L G4 G4H G4L G5 G5H G5L G6 G6H G6L
net class "High-Current Class": DC+ DC- U U_OUT V V_OUT W W_OUT
net class "Bleed Class": BLEED1 BLEED2 BLEED3
net class "DC- Class": +15V_U_LS +15V_V_LS +15V_W_LS -3V_U_LS -3V_V_LS -3V_W_LS DC- G2 G2H G2L G4 G4H G4L G6 G6H G6L S2 S4 S6
net class "W Class": +15V_W_HS -3V_W_HS G5 G5H G5L S5 W W_OUT
net class "V Class": +15V_V_HS -3V_V_HS G3 G3H G3L S3 V V_OUT
net class "U Class": +15V_U_HS -3V_U_HS G1 G1H G1L S1 U U_OUT
component class "08 - Resolver": C19 C23 C89 C90 C91 C92 C93 C94 C100 C102 C161 C165 C166 C167 C169 C170 C173 C174 C176 C177 C181 C183 D8 D9 D10 J17 Q1 R60 R62 R135 R136 R137 R138 R139 R140 R141 R143 R146 R148 R247 R249 R250 R252 R253 R257 R258 R261 R264 R265 R266 R267 R268 R269 R270 R271 R272 U39 U40 U41 U42
component class "02 - Power Stage": C110 C111 C112 C158 C159 C160 C162 C163 C164 D11 D12 D15 D16 HS1 J2 J3 J6 J7 J8 J13 J14 J15 J18 J19 J20 MH1 MH2 MH3 MH4 Q2 R1 R2 R3 R4 R5 R6 R7 R8 R9 R10 R11 R12 R77 R78 R80 R81 R115 R116 R118 R119 R133 R134 TP1 TP2 TP3 TP4 TP11 TP12 TP13 U26 U27 U28
component class "04 - Auxiliary Power": C5 C10 C11 C12 C13 C16 C31 C56 C64 C95 C96 C97 C98 C99 C101 C103 C104 C105 C106 C107 C108 C109 C117 C118 C128 C154 C155 C156 C157 C168 C171 C172 C175 C178 C179 C180 C182 C184 C185 C186 C187 C188 C189 C190 C191 C192 C193 C194 C195 C196 C197 C198 C199 C200 C201 C202 C203 D4 D5 D6 D7 D19 D20 J21 J22 L7 L8 L9 Q7 Q8 R142 R144 R145 R147 R149 R150 R151 R152 R153 R154 R155 R156 R245 R246 R248 R251 R254 R255 R256 R259 R260 R262 R263 R273 R274 R275 R276 TP5 TP6 TP7 TP8 TP9 TP10 TP14 TP15 U6 U8 U16 U24 U25 U29 U30 U31 U32 U43
component class "07 - Current-Temp Sense": C14 C15 C17 C18 C20 C21 C22 C24 C25 C45 C46 C123 C126 C130 C131 C132 C133 C135 C136 C137 C138 C139 C140 C143 C144 C145 R53 R55 R56 R58 R59 R61 R63 R85 R86 R88 R91 R113 R114 R117 R122 R125 R128 R199 R200 R201 R202 R203 R204 R205 R206 R207 R208 R209 R210 R211 R212 R213 U7 U14 U33 U34 U35 U37
component class "03 - Controller": C30 C44 C53 C63 C119 C120 C121 C122 C124 C141 C142 C148 C149 C150 C151 C152 C153 D1 D2 D3 J4 J5 J9 L10 R45 R46 R47 R48 R49 R50 R66 R71 R76 R79 R82 R84 R87 R89 R90 R92 R93 R96 R101 R102 R107 R108 R109 R110 R111 R112 R192 R193 R194 R195 R196 R197 R198 R221 R222 R223 R224 R225 R226 R227 R228 R229 R230 R231 R232 R233 R234 R235 R236 R237 R238 R239 R240 U5 U36 U38
component class "06 - Voltage Sense": C1 C2 C3 C4 C6 C7 C8 C9 C113 C114 C115 C116 C125 C127 C129 C134 J1 R13 R14 R15 R16 R17 R18 R19 R20 R21 R22 R23 R24 R25 R26 R27 R28 R29 R30 R31 R32 R33 R34 R35 R36 R37 R38 R39 R40 R41 R42 R43 R44 R51 R52 R54 R57 R157 R158 R159 R160 R161 R162 R163 R164 R165 R166 R167 R168 R169 R170 R171 R172 R173 R174 R175 R176 R177 R178 R179 R180 R181 R182 R183 R184 R185 R186 R187 R188 R189 R190 R191 U1 U2 U3 U4
component class "05 - Gate Drivers": C26 C27 C28 C29 C32 C33 C34 C35 C36 C37 C38 C39 C40 C41 C42 C43 C47 C48 C49 C50 C51 C52 C54 C55 C57 C58 C59 C60 C61 C62 C65 C66 C67 C68 C69 C70 C71 C72 C73 C74 C75 C76 C77 C78 C79 C80 C81 C82 C83 C84 C85 C86 C87 C88 C146 C147 L1 L2 L3 L4 L5 L6 R64 R65 R67 R68 R69 R70 R72 R73 R74 R75 R83 R94 R95 R97 R98 R99 R100 R103 R104 R105 R106 R120 R121 R123 R124 R126 R127 R129 R130 R131 R132 R214 R215 R216 R217 R218 R219 R220 U9 U10 U11 U12 U13 U15 U17 U18 U19 U20 U21 U22 U23

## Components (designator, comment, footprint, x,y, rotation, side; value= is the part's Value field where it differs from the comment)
C1 "C0603C472K3RAC7867" FP-C0603C-CF-IPC_B 6460,6040 r270 top value=4.7nF
C2 "CL10B103KA8WPNC" FP-C0603C-CF-IPC_B 6820,6040 r270 top value=10nF
C3 "CL10B103KA8WPNC" FP-C0603C-CF-IPC_B 7180,6040 r270 top value=10nF
C4 "CL10B103KA8WPNC" FP-C0603C-CF-IPC_B 7540,6040 r270 top value=10nF
C5 "C0603C104K3RACTU" FP-C0603C-CF-IPC_B 7480,5920 r180 top value=0.10μF
C6 "C0603C104K3RACTU" FP-C0603C-CF-IPC_B 6580,5795 r0 top value=0.10μF
C7 "C0603C104K3RACTU" FP-C0603C-CF-IPC_B 6940,5795 r0 top value=0.10μF
C8 "C0603C104K3RACTU" FP-C0603C-CF-IPC_B 7300,5795 r0 top value=0.10μF
C9 "C0603C104K3RACTU" FP-C0603C-CF-IPC_B 7660,5795 r0 top value=0.10μF
C10 "CL31B106KAHSFNE" FP-CL31-IPC_B 6425,5075 r0 top value=10μF
C11 "C0603C104K3RACTU" FP-C0603C-CF-IPC_B 7210,4580 r180 top value=0.10μF
C12 "CL31B106KAHSFNE" FP-CL31-IPC_B 5930,4545 r180 top value=10μF
C13 "C0603C104K3RACTU" FP-C0603C-CF-IPC_B 7210,4511 r180 top value=0.10μF
C14 "GRT188R61H225ME13D" FP-C0603C-CF-IPC_B 5930,4463 r180 top value=2.2μF
C15 "C0603C104K3RACTU" FP-C0603C-CF-IPC_B 6615,4442 r0 top value=0.10μF
C16 "C0603C104K3RACTU" FP-C0603C-CF-IPC_B 7210,4442 r180 top value=0.10μF
C17 "C0603C104K3RACTU" FP-C0603C-CF-IPC_B 5930,4395 r180 top value=0.10μF
C18 "C0603C104K3RACTU" FP-C0603C-CF-IPC_B 5930,4327 r180 top value=0.10μF
C19 "C0603C102K5RACAUTO" FP-C0603C-CF-IPC_B 7210,4306 r0 top value=1nF
C20 "C0603C331JAGAC7867" FP-C0603C-CF-IPC_B 6615,4238 r180 top value=330pF
C21 "C0603C472K3RAC7867" FP-C0603C-CF-IPC_B 6790,4238 r180 top value=4.7nF
C22 "C0603C472K3RAC7867" FP-C0603C-CF-IPC_B 6790,4170 r180 top value=4.7nF
C23 "C0603C102K5RACAUTO" FP-C0603C-CF-IPC_B 7210,4170 r0 top value=1nF
C24 "C0603C472K3RAC7867" FP-C0603C-CF-IPC_B 6790,4102 r180 top value=4.7nF
C25 "C0603C472K3RAC7867" FP-C0603C-CF-IPC_B 6790,3966 r180 top value=4.7nF
C26 "GRT188R61H225ME13D" FP-C0603C-CF-IPC_B 1425,3852 r180 top value=2.2μF
C27 "GRT188R61H225ME13D" FP-C0603C-CF-IPC_B 5575,3852 r180 top value=2.2μF
C28 "CL31B106KAHSFNE" FP-CL31-IPC_B 1930,3835 r180 top value=10μF
C29 "CL31B106KAHSFNE" FP-CL31-IPC_B 5070,3835 r180 top value=10μF
C30 "CL10C560JB8NNNC" FP-C0603C-CF-IPC_B 7210,3820 r180 top value=56pF
C31 "CL31B106KAHSFNE" FP-CL31-IPC_B 7575.81,3790 r180 top value=10μF
C32 "CL10C560JB8NNNC" FP-C0603C-CF-IPC_B 1425,3784 r180 top value=56pF
C33 "CL10C560JB8NNNC" FP-C0603C-CF-IPC_B 5575,3784 r0 top value=56pF
C34 "CL10C560JB8NNNC" FP-C0603C-CF-IPC_B 1425,3716 r180 top value=56pF
C35 "CL10C560JB8NNNC" FP-C0603C-CF-IPC_B 5575,3716 r0 top value=56pF
C36 "CL31B106KAHSFNE" FP-CL31-IPC_B 1930,3645 r0 top value=10μF
C37 "CL31B106KAHSFNE" FP-CL31-IPC_B 5070,3645 r0 top value=10μF
C38 "GRT188R61H225ME13D" FP-C0603C-CF-IPC_B 1425,3648 r0 top value=2.2μF
C39 "GRT188R61H225ME13D" FP-C0603C-CF-IPC_B 5575,3648 r0 top value=2.2μF
C40 "CL31B106KAHSFNE" FP-CL31-IPC_B 2135,3565 r180 top value=10μF
C41 "CL31B106KAHSFNE" FP-CL31-IPC_B 4865,3565 r0 top value=10μF
C42 "CL31B106KAHSFNE" FP-CL31-IPC_B 2135,3480 r0 top value=10μF
C43 "CL31B106KAHSFNE" FP-CL31-IPC_B 4865,3480 r180 top value=10μF
C44 "CL10C560JB8NNNC" FP-C0603C-CF-IPC_B 7210,3412 r0 top value=56pF
C45 "C0603C104K3RACTU" FP-C0603C-CF-IPC_B 6455,3344 r0 top value=0.10μF
C46 "C0603C104K3RACTU" FP-C0603C-CF-IPC_B 6790,3208 r0 top value=0.10μF
C47 "CL31B106KAHSFNE" FP-CL31-IPC_B 1135,3152 r180 top value=10μF
C48 "CL31B106KAHSFNE" FP-CL31-IPC_B 5865,3152 r180 top value=10μF
C49 "GRT188R61H225ME13D" FP-C0603C-CF-IPC_B 1425,3102 r180 top value=2.2μF
C50 "GRT188R61H225ME13D" FP-C0603C-CF-IPC_B 5575,3102 r180 top value=2.2μF
C51 "CL31B106KAHSFNE" FP-CL31-IPC_B 1930,3085 r180 top value=10μF
C52 "CL31B106KAHSFNE" FP-CL31-IPC_B 5070,3085 r180 top value=10μF
C53 "CL10C560JB8NNNC" FP-C0603C-CF-IPC_B 7210,3072 r0 top value=56pF
C54 "CL10C560JB8NNNC" FP-C0603C-CF-IPC_B 1425,3034 r180 top value=56pF
C55 "CL10C560JB8NNNC" FP-C0603C-CF-IPC_B 5575,3034 r0 top value=56pF
C56 "CL31B106KAHSFNE" FP-CL31-IPC_B 875,2960 r270 top value=10μF
C57 "CL10C560JB8NNNC" FP-C0603C-CF-IPC_B 1425,2966 r180 top value=56pF
C58 "CL10C560JB8NNNC" FP-C0603C-CF-IPC_B 5575,2966 r0 top value=56pF
C59 "CL31B106KAHSFNE" FP-CL31-IPC_B 1930,2895 r0 top value=10μF
C60 "CL31B106KAHSFNE" FP-CL31-IPC_B 5070,2895 r0 top value=10μF
C61 "GRT188R61H225ME13D" FP-C0603C-CF-IPC_B 1425,2898 r0 top value=2.2μF
C62 "GRT188R61H225ME13D" FP-C0603C-CF-IPC_B 5575,2898 r0 top value=2.2μF
C63 "CL10C560JB8NNNC" FP-C0603C-CF-IPC_B 7210,2868 r0 top value=56pF
C64 "CL31B106KAHSFNE" FP-CL31-IPC_B 875,2760 r90 top value=10μF
C65 "CL31B106KAHSFNE" FP-CL31-IPC_B 2135,2765 r180 top value=10μF
C66 "CL31B106KAHSFNE" FP-CL31-IPC_B 4865,2765 r0 top value=10μF
C67 "CL31B106KAHSFNE" FP-CL31-IPC_B 2135,2680 r0 top value=10μF
C68 "CL31B106KAHSFNE" FP-CL31-IPC_B 4865,2680 r180 top value=10μF
C69 "CL31B106KAHSFNE" FP-CL31-IPC_B 1135,2402 r180 top value=10μF
C70 "CL31B106KAHSFNE" FP-CL31-IPC_B 5865,2402 r180 top value=10μF
C71 "GRT188R61H225ME13D" FP-C0603C-CF-IPC_B 1425,2352 r180 top value=2.2μF
C72 "GRT188R61H225ME13D" FP-C0603C-CF-IPC_B 5575,2352 r180 top value=2.2μF
C73 "CL31B106KAHSFNE" FP-CL31-IPC_B 1930,2335 r180 top value=10μF
C74 "CL31B106KAHSFNE" FP-CL31-IPC_B 5070,2335 r180 top value=10μF
C75 "CL10C560JB8NNNC" FP-C0603C-CF-IPC_B 1425,2284 r180 top value=56pF
C76 "CL10C560JB8NNNC" FP-C0603C-CF-IPC_B 5575,2284 r0 top value=56pF
C77 "CL10C560JB8NNNC" FP-C0603C-CF-IPC_B 1425,2216 r180 top value=56pF
C78 "CL10C560JB8NNNC" FP-C0603C-CF-IPC_B 5575,2216 r0 top value=56pF
C79 "CL31B106KAHSFNE" FP-CL31-IPC_B 1930,2145 r0 top value=10μF
C80 "CL31B106KAHSFNE" FP-CL31-IPC_B 5070,2145 r0 top value=10μF
C81 "GRT188R61H225ME13D" FP-C0603C-CF-IPC_B 1425,2148 r0 top value=2.2μF
C82 "GRT188R61H225ME13D" FP-C0603C-CF-IPC_B 5575,2148 r0 top value=2.2μF
C83 "CL31B106KAHSFNE" FP-CL31-IPC_B 2135,2065 r180 top value=10μF
C84 "CL31B106KAHSFNE" FP-CL31-IPC_B 4865,2065 r0 top value=10μF
C85 "CL31B106KAHSFNE" FP-CL31-IPC_B 2135,1980 r0 top value=10μF
C86 "CL31B106KAHSFNE" FP-CL31-IPC_B 4865,1980 r180 top value=10μF
C87 "CL31B106KAHSFNE" FP-CL31-IPC_B 1135,1652 r180 top value=10μF
C88 "CL31B106KAHSFNE" FP-CL31-IPC_B 5865,1652 r180 top value=10μF
C89 "C0603C104K3RACTU" FP-C0603C-CF-IPC_B 7050,1363 r0 top value=0.10μF
C90 "CL10B103KA8WPNC" FP-C0603C-CF-IPC_B 7170,1295 r180 top value=10nF
C91 "C0603C102K5RACAUTO" FP-C0603C-CF-IPC_B 7050,1227 r180 top value=1nF
C92 "C0603C104K3RACTU" FP-C0603C-CF-IPC_B 7560,1160 r90 top value=0.10μF
C93 "06035A180JAT2A" FP-C0603C-CF-IPC_B 7320,1091 r0 top value=18pF
C94 "CL10B103KA8WPNC" FP-C0603C-CF-IPC_B 7170,1022 r0 top value=10nF
C95 "GCM1885C2A221JA16D" FP-C0603C-CF-IPC_B 6275,981 r180 top value=220pF
C96 "CL10C101JB8NNNC" FP-C0603C-CF-IPC_B 6395,981 r0 top value=100pF
C97 "GCM188R72A103KA37D" FP-C0603C-CF-IPC_B 5615,980 r180 top value=10nF
C98 "CGA3E2X7R1H683K080AA" FP-C0603C-CF-IPC_B 6155,913 r0 top value=68nF
C99 "C0603C102K5RACAUTO" FP-C0603C-CF-IPC_B 5615,910 r180 top value=1nF
C100 "C0603C104K3RACTU" FP-C0603C-CF-IPC_B 7320,840 r0 top value=0.10μF
C101 "GCM188R72A103KA37D" FP-C0603C-CF-IPC_B 6650,819 r0 top value=10nF
C102 "C0603C104K3RACTU" FP-C0603C-CF-IPC_B 7320,771 r0 top value=0.10μF
C103 "CGA3E1X7R1V105K080AC" FP-C0603C-CF-IPC_B 6650,750 r0 top value=1μF
C104 "C0603C472K3RAC7867" FP-C0603C-CF-IPC_B 6850,710 r0 top value=4.7nF
C105 "GRM188R6YA106MA73D" FP-C0603C-CF-IPC_B 6120,680 r270 top value=10μF
C106 "GRM188R6YA106MA73D" FP-C0603C-CF-IPC_B 6189,680 r270 top value=10μF
C107 "GRM188R6YA106MA73D" FP-C0603C-CF-IPC_B 6258,680 r270 top value=10μF
C108 "GRM188R6YA106MA73D" FP-C0603C-CF-IPC_B 6327,680 r270 top value=10μF
C109 "CL10C560JB8NNNC" FP-C0603C-CF-IPC_B 6650,478 r180 top value=56pF
C110 "C4AQQEW5650A3BJ" C4AQQEW5650A3BJ 3500,5850 r90 bottom value=65µF
C111 "C4AQQEW5650A3BJ" C4AQQEW5650A3BJ 5350,5850 r270 bottom value=65µF
C112 "C4AQQEW5650A3BJ" C4AQQEW5650A3BJ 1650,5850 r270 bottom value=65µF
C113 "CL10B103KA8WPNC" FP-C0603C-CF-IPC_B 7660,6040 r270 bottom value=10nF
C114 "CL10B103KA8WPNC" FP-C0603C-CF-IPC_B 7300,6040 r270 bottom value=10nF
C115 "CL10B103KA8WPNC" FP-C0603C-CF-IPC_B 6940,6040 r270 bottom value=10nF
C116 "C0603C472K3RAC7867" FP-C0603C-CF-IPC_B 6580,6040 r270 bottom value=4.7nF
C117 "C0603C104K3RACTU" FP-C0603C-CF-IPC_B 7480,5920 r0 bottom value=0.10μF
C118 "C0603C104K3RACTU" FP-C0603C-CF-IPC_B 7480,5710 r0 bottom value=0.10μF
C119 "C0603C472K3RAC7867" FP-C0603C-CF-IPC_B 7805,4918 r0 bottom value=4.7nF
C120 "06035A180JAT2A" FP-C0603C-CF-IPC_B 7805,4850 r180 bottom value=18pF
C121 "06035A180JAT2A" FP-C0603C-CF-IPC_B 7805,4782 r0 bottom value=18pF
C122 "CL10C560JB8NNNC" FP-C0603C-CF-IPC_B 7230,4616 r180 bottom value=56pF
C123 "C0603C104K3RACTU" FP-C0603C-CF-IPC_B 7100,4616 r0 bottom value=0.10μF
C124 "CL10C560JB8NNNC" FP-C0603C-CF-IPC_B 6785,4615 r180 bottom value=56pF
C125 "GCM188R71C274KA37D" FP-GCM188-0_1-IPC_A 6785,4548 r180 bottom value=0.27μF
C126 "GRT188R61H225ME13D" FP-C0603C-CF-IPC_B 6625,4548 r0 bottom value=2.2μF
C127 "GCM188R71C274KA37D" FP-GCM188-0_1-IPC_A 6785,4480 r180 bottom value=0.27μF
C128 "CL31B106KAHSFNE" FP-CL31-IPC_B 7850,4395 r90 bottom value=10μF
C129 "GCM188R71C274KA37D" FP-GCM188-0_1-IPC_A 6785,4411 r180 bottom value=0.27μF
C130 "C0603C472K3RAC7867" FP-C0603C-CF-IPC_B 7230,4411 r180 bottom value=4.7nF
C131 "CL10C101JB8NNNC" FP-C0603C-CF-IPC_B 7100,4411 r180 bottom value=100pF
C132 "CL10C101JB8NNNC" FP-C0603C-CF-IPC_B 6970,4411 r0 bottom value=100pF
C133 "C0603C331JAGAC7867" FP-C0603C-CF-IPC_B 6625,4411 r180 bottom value=330pF
C134 "GCM188R71C274KA37D" FP-GCM188-0_1-IPC_A 6785,4343 r180 bottom value=0.27μF
C135 "C0603C104K3RACTU" FP-C0603C-CF-IPC_B 7100,4343 r0 bottom value=0.10μF
C136 "C0603C104K3RACTU" FP-C0603C-CF-IPC_B 6625,4343 r0 bottom value=0.10μF
C137 "C0603C472K3RAC7867" FP-C0603C-CF-IPC_B 7230,4139 r180 bottom value=4.7nF
C138 "CL10C101JB8NNNC" FP-C0603C-CF-IPC_B 7100,4139 r180 bottom value=100pF
C139 "CL10C101JB8NNNC" FP-C0603C-CF-IPC_B 6970,4139 r0 bottom value=100pF
C140 "C0603C104K3RACTU" FP-C0603C-CF-IPC_B 7100,4070 r0 bottom value=0.10μF
C141 "C0603C104K3RACTU" FP-C0603C-CF-IPC_B 7885,3868 r0 bottom value=0.10μF
C142 "C0603C104K3RACTU" FP-C0603C-CF-IPC_B 7535,3868 r180 bottom value=0.10μF
C143 "C0603C472K3RAC7867" FP-C0603C-CF-IPC_B 7230,3868 r180 bottom value=4.7nF
C144 "CL10C101JB8NNNC" FP-C0603C-CF-IPC_B 7100,3868 r180 bottom value=100pF
C145 "CL10C101JB8NNNC" FP-C0603C-CF-IPC_B 6970,3868 r0 bottom value=100pF
C146 "CL10C560JB8NNNC" FP-C0603C-CF-IPC_B 6785,3500 r0 bottom value=56pF
C147 "GRT188R61H225ME13D" FP-C0603C-CF-IPC_B 6625,3500 r0 bottom value=2.2μF
C148 "CL10C560JB8NNNC" FP-C0603C-CF-IPC_B 7231.42,3465 r180 bottom value=56pF
C149 "CL10C560JB8NNNC" FP-C0603C-CF-IPC_B 7510,3154 r180 bottom value=56pF
C150 "C0603C104K3RACTU" FP-C0603C-CF-IPC_B 7030,3058 r180 bottom value=0.10μF
C151 "C0603C104K3RACTU" FP-C0603C-CF-IPC_B 7030,2785 r0 bottom value=0.10μF
C152 "C0603C104K3RACTU" FP-C0603C-CF-IPC_B 7030,2716 r0 bottom value=0.10μF
C153 "GRT188R61H225ME13D" FP-C0603C-CF-IPC_B 7490,2625 r0 bottom value=2.2μF
C154 "CL31B106KAHSFNE" FP-CL31-IPC_B 7140,1840 r270 bottom value=10μF
C155 "CL31B106KAHSFNE" FP-CL31-IPC_B 6765,1840 r270 bottom value=10μF
C156 "CL31B106KAHSFNE" FP-CL31-IPC_B 7140,1640 r90 bottom value=10μF
C157 "CL31B106KAHSFNE" FP-CL31-IPC_B 6765,1640 r90 bottom value=10μF
C158 "CL31B475KBHNFNE" FP-CL31-IPC_C 5380,1360 r0 bottom value=4.7μF
C159 "CL31B475KBHNFNE" FP-CL31-IPC_C 3990,1360 r0 bottom value=4.7μF
C160 "CL31B475KBHNFNE" FP-CL31-IPC_C 2600,1360 r0 bottom value=4.7μF
C161 "C0603C104K3RACTU" FP-C0603C-CF-IPC_B 7800,1285 r180 bottom value=0.10μF
C162 "CL31B475KBHNFNE" FP-CL31-IPC_C 5380,1250 r180 bottom value=4.7μF
C163 "CL31B475KBHNFNE" FP-CL31-IPC_C 3990,1250 r180 bottom value=4.7μF
C164 "CL31B475KBHNFNE" FP-CL31-IPC_C 2600,1250 r180 bottom value=4.7μF
C165 "C0603C331JAGAC7867" FP-C0603C-CF-IPC_B 7800,1215 r180 bottom value=330pF
C166 "C0603C472K3RAC7867" FP-C0603C-CF-IPC_B 6960,1194 r180 bottom value=4.7nF
C167 "06035A180JAT2A" FP-C0603C-CF-IPC_B 7200,1126 r180 bottom value=18pF
C168 "CGA3E2X7R1H473K080AA" FP-C0603C-CF-IPC_B 6155,1038 r180 bottom value=47nF
C169 "C0603C104K3RACTU" FP-C0603C-CF-IPC_B 7200,990 r0 bottom value=0.10μF
C170 "C0603C104K3RACTU" FP-C0603C-CF-IPC_B 6960,990 r0 bottom value=0.10μF
C171 "GCM188R71E224KA55D" FP-C0603C-CF-IPC_B 6155,900 r180 bottom value=220nF
C172 "CGA3E2X7R1H104K080AA" FP-C0603C-CF-IPC_B 5755,900 r180 bottom value=100nF
C173 "C0603C470J1GACTU" FP-C0603C-CF-IPC_B 7620,865 r90 bottom value=47pF
C174 "C0603C331JAGAC7867" FP-C0603C-CF-IPC_B 7290,865 r90 bottom value=330pF
C175 "GRM188R6YA106MA73D" FP-C0603C-CF-IPC_B 5755,830 r180 bottom value=10μF
C176 "C0603C470J1GACTU" FP-C0603C-CF-IPC_B 7620,745 r90 bottom value=47pF
C177 "C0603C331JAGAC7867" FP-C0603C-CF-IPC_B 7290,745 r90 bottom value=330pF
C178 "GRM188R6YA106MA73D" FP-C0603C-CF-IPC_B 5755,760 r180 bottom value=10μF
C179 "GRM188R6YA106MA73D" FP-C0603C-CF-IPC_B 5755,690 r180 bottom value=10μF
C180 "C0603C104K3RACTU" FP-C0603C-CF-IPC_B 7680,652 r0 bottom value=0.10μF
C181 "C0603C331JAGAC7867" FP-C0603C-CF-IPC_B 7800,583 r0 bottom value=330pF
C182 "C0603C104K3RACTU" FP-C0603C-CF-IPC_B 7680,583 r0 bottom value=0.10μF
C183 "C0603C104K3RACTU" FP-C0603C-CF-IPC_B 7800,513 r0 bottom value=0.10μF
C184 "C0603C104K3RACTU" FP-C0603C-CF-IPC_B 7680,513 r0 bottom value=0.10μF
C185 "C0603C681J5GACTU" FP-C0603C-CF-IPC_B 6405,300 r90 bottom value=680pF
C186 "GRM188R6YA106MA73D" FP-C0603C-CF-IPC_B 6335,300 r270 bottom value=10μF
C187 "GRM188R6YA106MA73D" FP-C0603C-CF-IPC_B 6265,300 r270 bottom value=10μF
C188 "CGA3E1X7R1V105K080AC" FP-C0603C-CF-IPC_B 6195,300 r270 bottom value=1μF
C189 "CGA3E2X7R1H104K080AA" FP-C0603C-CF-IPC_B 6125,300 r270 bottom value=100nF
C190 "CGA3E2X7R1H104K080AA" FP-C0603C-CF-IPC_B 6055,300 r90 bottom value=100nF
C191 "CGA3E1X7R1V105K080AC" FP-C0603C-CF-IPC_B 5985,300 r90 bottom value=1μF
C192 "GRM188R6YA106MA73D" FP-C0603C-CF-IPC_B 5915,300 r90 bottom value=10μF
C193 "GRM188R6YA106MA73D" FP-C0603C-CF-IPC_B 5845,300 r90 bottom value=10μF
C194 "C0603C681J5GACTU" FP-C0603C-CF-IPC_B 5775,300 r90 bottom value=680pF
C195 "GRM188R6YA106MA73D" FP-C0603C-CF-IPC_B 6335,130 r90 bottom value=10μF
C196 "GRM188R6YA106MA73D" FP-C0603C-CF-IPC_B 6265,130 r90 bottom value=10μF
C197 "GRM188R6YA106MA73D" FP-C0603C-CF-IPC_B 6195,130 r90 bottom value=10μF
C198 "GRM188R6YA106MA73D" FP-C0603C-CF-IPC_B 6125,130 r90 bottom value=10μF
C199 "GRM188R6YA106MA73D" FP-C0603C-CF-IPC_B 6055,130 r270 bottom value=10μF
C200 "GRM188R6YA106MA73D" FP-C0603C-CF-IPC_B 5985,130 r270 bottom value=10μF
C201 "GRM188R6YA106MA73D" FP-C0603C-CF-IPC_B 5915,130 r270 bottom value=10μF
C202 "GRM188R6YA106MA73D" FP-C0603C-CF-IPC_B 5845,130 r270 bottom value=10μF
C203 "CL31B106KAHSFNE" FP-CL31-IPC_B 6850,105 r0 bottom value=10μF
D1 "CMD17-21VRD/TR8" FP-LTST-C171GKT-MFG-RED 7435,3018 r0 top value=RED
D2 "LTST-C171KSKT" FP-LTST-C171GKT-MFG-YELLOW 7435,2936 r0 top value=YELLOW
D3 "LTST-C171GKT" FP-LTST-C171GKT-MFG 7435,2854 r0 top value=GREEN
D4 "LTST-C171GKT" FP-LTST-C171GKT-MFG 6645,1420 r0 top value=GREEN
D5 "LTST-C171GKT" FP-LTST-C171GKT-MFG 6645,1335 r0 top value=GREEN
D6 "LTST-C171GKT" FP-LTST-C171GKT-MFG 6645,1250 r0 top value=GREEN
D7 "LTST-C171GKT" FP-LTST-C171GKT-MFG 6645,1170 r0 top value=GREEN
D8 "BAS40DW-04-TP" SOT65P222X120-6N 7550,1020 r90 top value=N/A
D9 "BAS40DW-04-TP" SOT65P222X120-6N 7550,840 r90 top value=N/A
D10 "BAS40DW-04-TP" SOT65P222X120-6N 7550,660 r90 top value=N/A
D11 "APTR3216-VFX" FP-APTR3216SECK-MFG 6216.53,3700 r180 bottom value=PURPLE
D12 "APTR3216-VFX" FP-APTR3216SECK-MFG 783.47,3700 r180 bottom value=PURPLE
D13 "SMD26PL-TP" ONSC-SOD-123FL-2-498-01_V 7750,2915 r270 bottom value=N/A
D14 "SMD26PL-TP" ONSC-SOD-123FL-2-498-01_V 7750,2585 r270 bottom value=N/A
D15 "APTR3216-VFX" FP-APTR3216SECK-MFG 6216.53,2300 r180 bottom value=PURPLE
D16 "APTR3216-VFX" FP-APTR3216SECK-MFG 783.47,2300 r180 bottom value=PURPLE
D17 "SMD26PL-TP" ONSC-SOD-123FL-2-498-01_V 7865,1940 r0 bottom value=N/A
D18 "SMD26PL-TP" ONSC-SOD-123FL-2-498-01_V 7865,1385 r0 bottom value=N/A
D19 "PMEG060V100EPE-QZ" FP-PSMC_TO-277A-MFG 6215,505 r0 bottom value=N/A
D20 "PMEG060V100EPE-QZ" FP-PSMC_TO-277A-MFG 5965,505 r0 bottom value=N/A
HS1 "LA6/150 12V" "LA 6 150 12" 3500,3000 r180 bottom locked value=N/A
J1 "1755778" 1755778 6750,7835 r180 top value=N/A
J2 "7460307" 7460307 2110,7400 r0 top value=N/A
J3 "7460307" 7460307 4890,7400 r0 top value=N/A
J4 "L717SDE09PA4CH4RC309" L717SDE09PA4CH4RC309 7630,5020 r90 top locked value=N/A
J5 "640456-4" TECO-640456-4 7315,5275 r90 top value=N/A
J6 "0734151471" FP-73415-1471-MFG 2900,3800 r0 top value=N/A
J7 "0734151471" FP-73415-1471-MFG 3500,3800 r0 top value=N/A
J8 "0734151471" FP-73415-1471-MFG 4100,3800 r0 top value=N/A
J9 "61301221121" FP-61301221121-MFG 7887,3400 r270 top value=N/A
J10 "1881558" CONN_1881558 7832,2915 r90 top value=N/A
J11 "1881558" CONN_1881558 7832,2585 r90 top value=N/A
J12 "1755736" 1755736 7837,2140 r90 top value=N/A
J13 "0734151471" FP-73415-1471-MFG 2900,2200 r0 top value=N/A
J14 "0734151471" FP-73415-1471-MFG 3500,2200 r0 top value=N/A
J15 "0734151471" FP-73415-1471-MFG 4100,2200 r0 top value=N/A
J16 "1755736" 1755736 7837,1585 r90 top value=N/A
J17 "61200621621" 61200621621 7810,890 r270 top value=N/A
J18 "7460307" 7460307 2110,600 r0 top value=N/A
J19 "7460307" 7460307 3500,600 r0 top value=N/A
J20 "7460307" 7460307 4890,600 r0 top value=N/A
J21 "PJ-102AH" CUI-PJ-102B_V 7170,428.11 r270 top value=N/A
J22 "1808190" 1808190 7295,155 r180 bottom value=N/A
L1 "744226S" WE-SL2 1135,3400 r270 top value=10μH
L2 "744226S" WE-SL2 5865,3400 r270 top value=10μH
L3 "744226S" WE-SL2 1135,2650 r270 top value=10μH
L4 "744226S" WE-SL2 5865,2650 r270 top value=10μH
L5 "744226S" WE-SL2 1135,1900 r270 top value=10μH
L6 "744226S" WE-SL2 5865,1900 r270 top value=10μH
L7 "74439358100" WE-XHMI_8080_L8.8W8.3H7.8 5880,830 r90 top value=10μH
L8 "74437368220" 74437368220 5795,320 r270 top value=22µH
L9 "74437368220" 74437368220 6230,320 r90 top value=22µH
L10 "DLW43SH101XK2L" FP-DLW43-0_2-t2_6-e0_6-MFG 7805,4670 r0 bottom value=100µH
MH1 "MH_M4_P" MH_M4_P 250,7750 r0 top locked value=N/A
MH2 "MH_M4_P" MH_M4_P 7750,7750 r0 top locked value=N/A
MH3 "MH_M4_P" MH_M4_P 250,250 r0 top locked value=N/A
MH4 "MH_M4_P" MH_M4_P 7750,250 r0 top locked value=N/A
Q1 "BC817-16LT3G" ONSC-SOT-23-3-318-08_V 7050,1120 r0 top value=N/A
Q2 "CCB021M12FM3T" FM3_SIX-PACK_3PHASE_CRW 3500,3000 r0 bottom locked value=N/A
Q3 "DMN6140L-13" FP-SOT23-MFG 7650,2915 r0 bottom value=N/A
Q4 "DMN6140L-13" FP-SOT23-MFG 7650,2585 r0 bottom value=N/A
Q5 "MJD44H11T4G" ONSC-DPAK-3-369C-01_V 7615,2145 r90 bottom value=N/A
Q6 "MJD44H11T4G" ONSC-DPAK-3-369C-01_V 7615,1590 r90 bottom value=N/A
Q7 "DMT12H007LPS-13" FP-PowerDI5060-8-MFG 6910,710 r90 bottom value=N/A
Q8 "DMT12H007LPS-13" FP-PowerDI5060-8-MFG 6910,460 r90 bottom value=N/A
R1 "CRGP2512F220K" FP-CRGP2512-IPC_C 2900,7650 r180 top value=220kΩ
R2 "CRGP2512F220K" FP-CRGP2512-IPC_C 3300,7650 r180 top value=220kΩ
R3 "CRGP2512F220K" FP-CRGP2512-IPC_C 3700,7650 r180 top value=220kΩ
R4 "CRGP2512F220K" FP-CRGP2512-IPC_C 4100,7650 r180 top value=220kΩ
R5 "CRGP2512F220K" FP-CRGP2512-IPC_C 2900,7450 r180 top value=220kΩ
R6 "CRGP2512F220K" FP-CRGP2512-IPC_C 3300,7450 r180 top value=220kΩ
R7 "CRGP2512F220K" FP-CRGP2512-IPC_C 3700,7450 r180 top value=220kΩ
R8 "CRGP2512F220K" FP-CRGP2512-IPC_C 4100,7450 r180 top value=220kΩ
R9 "CRGP2512F220K" FP-CRGP2512-IPC_C 2900,7250 r180 top value=220kΩ
R10 "CRGP2512F220K" FP-CRGP2512-IPC_C 3300,7250 r180 top value=220kΩ
R11 "CRGP2512F220K" FP-CRGP2512-IPC_C 3700,7250 r180 top value=220kΩ
R12 "CRGP2512F220K" FP-CRGP2512-IPC_C 4100,7250 r180 top value=220kΩ
R13 "TNPW1206249KBEEA" RESC3216X65X50NL15T25 6580,7150 r270 top value=249kΩ
R14 "TNPW1206249KBEEA" RESC3216X65X50NL15T25 6940,7150 r270 top value=249kΩ
R15 "TNPW1206249KBEEA" RESC3216X65X50NL15T25 7300,7150 r270 top value=249kΩ
R16 "TNPW1206249KBEEA" RESC3216X65X50NL15T25 7660,7150 r270 top value=249kΩ
R17 "TNPW1206249KBEEA" RESC3216X65X50NL15T25 6580,6960 r270 top value=249kΩ
R18 "TNPW1206249KBEEA" RESC3216X65X50NL15T25 6940,6960 r270 top value=249kΩ
R19 "TNPW1206249KBEEA" RESC3216X65X50NL15T25 7300,6960 r270 top value=249kΩ
R20 "TNPW1206249KBEEA" RESC3216X65X50NL15T25 7660,6960 r270 top value=249kΩ
R21 "TNPW1206249KBEEA" RESC3216X65X50NL15T25 6580,6770 r270 top value=249kΩ
R22 "TNPW1206249KBEEA" RESC3216X65X50NL15T25 6940,6770 r270 top value=249kΩ
R23 "TNPW1206249KBEEA" RESC3216X65X50NL15T25 7300,6770 r270 top value=249kΩ
R24 "TNPW1206249KBEEA" RESC3216X65X50NL15T25 7660,6770 r270 top value=249kΩ
R25 "TNPW1206249KBEEA" RESC3216X65X50NL15T25 6580,6580 r270 top value=249kΩ
R26 "TNPW1206249KBEEA" RESC3216X65X50NL15T25 6940,6580 r270 top value=249kΩ
R27 "TNPW1206249KBEEA" RESC3216X65X50NL15T25 7300,6580 r270 top value=249kΩ
R28 "TNPW1206249KBEEA" RESC3216X65X50NL15T25 7660,6580 r270 top value=249kΩ
R29 "TNPW1206249KBEEA" RESC3216X65X50NL15T25 6580,6390 r270 top value=249kΩ
R30 "TNPW1206249KBEEA" RESC3216X65X50NL15T25 6940,6390 r270 top value=249kΩ
R31 "TNPW1206249KBEEA" RESC3216X65X50NL15T25 7300,6390 r270 top value=249kΩ
R32 "TNPW1206249KBEEA" RESC3216X65X50NL15T25 7660,6390 r270 top value=249kΩ
R33 "TNPW1206249KBEEA" RESC3216X65X50NL15T25 6580,6200 r270 top value=249kΩ
R34 "TNPW1206249KBEEA" RESC3216X65X50NL15T25 6940,6200 r270 top value=249kΩ
R35 "TNPW1206249KBEEA" RESC3216X65X50NL15T25 7300,6200 r270 top value=249kΩ
R36 "TNPW1206249KBEEA" RESC3216X65X50NL15T25 7660,6200 r270 top value=249kΩ
R37 "RC0603FR-074K99L" FP-MCR03-IPC_B 6580,6040 r270 top value=4.99kΩ
R38 "ERJ-PB3B3741V" FP-MCR03-IPC_B 6700,6040 r90 top value=3.74kΩ
R39 "RC0603FR-074K99L" FP-MCR03-IPC_B 6940,6040 r270 top value=4.99kΩ
R40 "CRCW06034K70FKTA" FP-MCR03-IPC_B 7060,6040 r270 top value=4.7kΩ
R41 "RC0603FR-074K99L" FP-MCR03-IPC_B 7300,6040 r270 top value=4.99kΩ
R42 "CRCW06034K70FKTA" FP-MCR03-IPC_B 7420,6040 r270 top value=4.7kΩ
R43 "RC0603FR-074K99L" FP-MCR03-IPC_B 7660,6040 r270 top value=4.99kΩ
R44 "CRCW06034K70FKTA" FP-MCR03-IPC_B 7780,6040 r270 top value=4.7kΩ
R45 "ERJ3EKF1002V" FP-MCR03-IPC_B 6790,4784 r0 top value=10kΩ
R46 "ERJ3EKF1002V" FP-MCR03-IPC_B 7210,4784 r180 top value=10kΩ
R47 "CRCW06030000Z0EB" FP-MCR03-IPC_B 6790,4716 r180 top value=0Ω
R48 "CRCW06030000Z0EB" FP-MCR03-IPC_B 7210,4716 r180 top value=0Ω
R49 "CRCW06030000Z0EB" FP-MCR03-IPC_B 6790,4648 r0 top value=0Ω
R50 "CRCW06030000Z0EB" FP-MCR03-IPC_B 7210,4648 r180 top value=0Ω
R51 "ERJ-3EKF49R9V" FP-MCR03-IPC_B 6790,4580 r0 top value=49.9Ω
R52 "ERJ-3EKF49R9V" FP-MCR03-IPC_B 6790,4511 r0 top value=49.9Ω
R53 "RC0603FR-072K2L" FP-MCR03-IPC_B 5800,4463 r180 top value=2.2kΩ
R54 "ERJ-3EKF49R9V" FP-MCR03-IPC_B 6790,4442 r0 top value=49.9Ω
R55 "ERJ-PB3B1801V" FP-MCR03-IPC_B 5800,4395 r0 top value=1.8kΩ
R56 "ERA3AEB4021V" FP-MCR03-IPC_B 6615,4374 r180 top value=4.02kΩ
R57 "ERJ-3EKF49R9V" FP-MCR03-IPC_B 6790,4374 r0 top value=49.9Ω
R58 "ERA3AEB4021V" FP-MCR03-IPC_B 6615,4306 r180 top value=4.02kΩ
R59 "ERJ-3EKF49R9V" FP-MCR03-IPC_B 6790,4306 r0 top value=49.9Ω
R60 "RT0603DRE072KL" FP-MCR03-IPC_B 7210,4238 r180 top value=2kΩ
R61 "ERA3AEB4021V" FP-MCR03-IPC_B 6615,4170 r180 top value=4.02kΩ
R62 "RT0603DRE072KL" FP-MCR03-IPC_B 7210,4102 r180 top value=2kΩ
R63 "ERJ-3EKF49R9V" FP-MCR03-IPC_B 6790,4034 r0 top value=49.9Ω
R64 "ERJ3EKF1002V" FP-MCR03-IPC_B 2135,3888 r0 top value=10kΩ
R65 "ERJ3EKF1002V" FP-MCR03-IPC_B 4865,3888 r180 top value=10kΩ
R66 "ERJ3EKF1002V" FP-MCR03-IPC_B 7210,3888 r0 top value=10kΩ
R67 "CRCW12100000Z0EAHP" RESC3125X70X40NL20T20 2135,3788 r0 top value=0Ω
R68 "RCWE1210R910FKEA" RESC3125X70X40NL20T20 4865,3788 r180 top value=0.91Ω
R69 "ERJ-3EKF49R9V" FP-MCR03-IPC_B 1300,3784 r0 top value=49.9Ω
R70 "ERJ-3EKF49R9V" FP-MCR03-IPC_B 5700,3784 r180 top value=49.9Ω
R71 "ERJ3EKF1002V" FP-MCR03-IPC_B 7210,3752 r180 top value=10kΩ
R72 "ERJ-3EKF49R9V" FP-MCR03-IPC_B 1300,3716 r0 top value=49.9Ω
R73 "ERJ-3EKF49R9V" FP-MCR03-IPC_B 5700,3716 r180 top value=49.9Ω
R74 "RCWE1210R910FKEA" RESC3125X70X40NL20T20 2135,3672 r0 top value=0.91Ω
R75 "CRCW12100000Z0EAHP" RESC3125X70X40NL20T20 4865,3672 r180 top value=0Ω
R76 "CRCW06030000Z0EB" FP-MCR03-IPC_B 7210,3684 r180 top value=0Ω
R77 "RC1206FR-07249RL" FP-MCR18-IPC_A 830,3610 r0 top value=249Ω
R78 "RC1206FR-07249RL" FP-MCR18-IPC_A 6170,3610 r0 top value=249Ω
R79 "CRCW06030000Z0EB" FP-MCR03-IPC_B 7210,3616 r180 top value=0Ω
R80 "RC1206FR-07249RL" FP-MCR18-IPC_A 830,3530 r180 top value=249Ω
R81 "RC1206FR-07249RL" FP-MCR18-IPC_A 6170,3530 r0 top value=249Ω
R82 "CRCW06030000Z0EB" FP-MCR03-IPC_B 7210,3548 r180 top value=0Ω
R83 "ERJ-3EKF49R9V" FP-MCR03-IPC_B 6790,3480 r180 top value=49.9Ω
R84 "CRCW06030000Z0EB" FP-MCR03-IPC_B 7210,3480 r180 top value=0Ω
R85 "CRCW06030000Z0EB" FP-MCR03-IPC_B 6790,3412 r180 top value=0Ω
R86 "RC0603FR-075K49L" FP-MCR03-IPC_B 6790,3344 r180 top value=5.49kΩ
R87 "ERJ3EKF1002V" FP-MCR03-IPC_B 7210,3344 r180 top value=10kΩ
R88 "RC0603FR-13330RL" FP-MCR03-IPC_B 6790,3276 r180 top value=330Ω
R89 "ERJ3EKF1002V" FP-MCR03-IPC_B 7210,3276 r0 top value=10kΩ
R90 "ERJ3EKF1002V" FP-MCR03-IPC_B 7210,3208 r0 top value=10kΩ
R91 "NCU18XH103F6SRB" FP-NCU18-0_15-IPC_B 6455,3140 r180 top value="10kΩ @25C"
R92 "CRCW060320K0FKTA" FP-MCR03-IPC_B 6790,3140 r180 top value=20kΩ
R93 "ERJ3EKF1002V" FP-MCR03-IPC_B 7210,3140 r180 top value=10kΩ
R94 "ERJ3EKF1002V" FP-MCR03-IPC_B 2135,3138 r0 top value=10kΩ
R95 "ERJ3EKF1002V" FP-MCR03-IPC_B 4865,3138 r180 top value=10kΩ
R96 "CRCW060320K0FKTA" FP-MCR03-IPC_B 6790,3072 r0 top value=20kΩ
R97 "CRCW12100000Z0EAHP" RESC3125X70X40NL20T20 2135,3038 r0 top value=0Ω
R98 "RCWE1210R910FKEA" RESC3125X70X40NL20T20 4865,3038 r180 top value=0.91Ω
R99 "ERJ-3EKF49R9V" FP-MCR03-IPC_B 1300,3034 r0 top value=49.9Ω
R100 "ERJ-3EKF49R9V" FP-MCR03-IPC_B 5700,3034 r180 top value=49.9Ω
R101 "CRCW060320K0FKTA" FP-MCR03-IPC_B 6790,3004 r0 top value=20kΩ
R102 "ERJ3EKF1002V" FP-MCR03-IPC_B 7210,3004 r180 top value=10kΩ
R103 "ERJ-3EKF49R9V" FP-MCR03-IPC_B 1300,2966 r0 top value=49.9Ω
R104 "ERJ-3EKF49R9V" FP-MCR03-IPC_B 5700,2966 r180 top value=49.9Ω
R105 "RCWE1210R910FKEA" RESC3125X70X40NL20T20 2135,2922 r0 top value=0.91Ω
R106 "CRCW12100000Z0EAHP" RESC3125X70X40NL20T20 4865,2922 r180 top value=0Ω
R107 "CRCW060320K0FKTA" FP-MCR03-IPC_B 6790,2936 r180 top value=20kΩ
R108 "ERJ3EKF1002V" FP-MCR03-IPC_B 7210,2936 r180 top value=10kΩ
R109 "CRCW060320K0FKTA" FP-MCR03-IPC_B 6790,2868 r180 top value=20kΩ
R110 "CRCW060320K0FKTA" FP-MCR03-IPC_B 6790,2800 r0 top value=20kΩ
R111 "CRCW060320K0FKTA" FP-MCR03-IPC_B 7210,2800 r180 top value=20kΩ
R112 "CRCW060320K0FKTA" FP-MCR03-IPC_B 7210,2732 r180 top value=20kΩ
R113 "CRCW2010165RFKEF" FP-CRCW2010-e3-IPC_B 6510,2530 r0 top value=165Ω
R114 "RT0603DRE072KL" FP-MCR03-IPC_B 6685,2535 r0 top value=2kΩ
R115 "RC1206FR-07249RL" FP-MCR18-IPC_A 830,2470 r180 top value=249Ω
R116 "RC1206FR-07249RL" FP-MCR18-IPC_A 6170,2470 r0 top value=249Ω
R117 "CRCW2010165RFKEF" FP-CRCW2010-e3-IPC_B 6510,2400 r0 top value=165Ω
R118 "RC1206FR-07249RL" FP-MCR18-IPC_A 830,2390 r180 top value=249Ω
R119 "RC1206FR-07249RL" FP-MCR18-IPC_A 6170,2390 r0 top value=249Ω
R120 "ERJ3EKF1002V" FP-MCR03-IPC_B 2135,2388 r0 top value=10kΩ
R121 "ERJ3EKF1002V" FP-MCR03-IPC_B 4865,2388 r180 top value=10kΩ
R122 "RT0603DRE072KL" FP-MCR03-IPC_B 6685,2385 r0 top value=2kΩ
R123 "CRCW12100000Z0EAHP" RESC3125X70X40NL20T20 2135,2288 r0 top value=0Ω
R124 "RCWE1210R910FKEA" RESC3125X70X40NL20T20 4865,2288 r180 top value=0.91Ω
R125 "CRCW2010165RFKEF" FP-CRCW2010-e3-IPC_B 6510,2270 r0 top value=165Ω
R126 "ERJ-3EKF49R9V" FP-MCR03-IPC_B 1300,2284 r0 top value=49.9Ω
R127 "ERJ-3EKF49R9V" FP-MCR03-IPC_B 5700,2284 r180 top value=49.9Ω
R128 "RT0603DRE072KL" FP-MCR03-IPC_B 6685,2235 r0 top value=2kΩ
R129 "ERJ-3EKF49R9V" FP-MCR03-IPC_B 1300,2216 r0 top value=49.9Ω
R130 "ERJ-3EKF49R9V" FP-MCR03-IPC_B 5700,2216 r180 top value=49.9Ω
R131 "RCWE1210R910FKEA" RESC3125X70X40NL20T20 2135,2172 r0 top value=0.91Ω
R132 "CRCW12100000Z0EAHP" RESC3125X70X40NL20T20 4865,2172 r180 top value=0Ω
R133 "CRCW12100000Z0EAHP" RESC3125X70X40NL20T20 6180,1710 r90 top value=0Ω
R134 "CRCW12100000Z0EAHP" RESC3125X70X40NL20T20 6310,1710 r90 top value=0Ω
R135 "ERJ3EKF1002V" FP-MCR03-IPC_B 7050,1432 r0 top value=10kΩ
R136 "CRCW060320K0FKTA" FP-MCR03-IPC_B 7170,1432 r180 top value=20kΩ
R137 "RC0603FR-07100KL" FP-MCR03-IPC_B 7170,1363 r0 top value=100kΩ
R138 "ERJ3EKF1002V" FP-MCR03-IPC_B 7050,1295 r180 top value=10kΩ
R139 "ERJ3EKF1002V" FP-MCR03-IPC_B 7170,1227 r180 top value=10kΩ
R140 "RC0603JR-0720RL" FP-MCR03-IPC_B 7170,1159 r0 top value=20Ω
R141 "ERJ3EKF1002V" FP-MCR03-IPC_B 7170,1091 r180 top value=10kΩ
R142 "RC0603FR-075K49L" FP-MCR03-IPC_B 6155,1045 r0 top value=5.49kΩ
R143 "RC0603FR-07470KL" FP-MCR03-IPC_B 7320,1022 r0 top value=470kΩ
R144 "RT0603DRE0771K5L" FP-MCR03-IPC_B 6155,980 r180 top value=71.5kΩ
R145 "RT0603FRE0749K9L" FP-MCR03-IPC_B 6650,956 r180 top value=49.9kΩ
R146 "RC0603FR-07100KL" FP-MCR03-IPC_B 7170,954 r180 top value=100kΩ
R147 "RC0603FR-0724K9L" FP-MCR03-IPC_B 6650,888 r0 top value=24.9kΩ
R148 "CRCW060320K0FKTA" FP-MCR03-IPC_B 7170,886 r0 top value=20kΩ
R149 "RC0603FR-0761K9L" FP-MCR03-IPC_B 6155,844 r0 top value=61.9kΩ
R150 "RC0603FR-07100KL" FP-MCR03-IPC_B 6650,682 r0 top value=100kΩ
R151 "RT0603DRE072KL" FP-MCR03-IPC_B 6850,640 r0 top value=2kΩ
R152 "RC0603FR-07100KL" FP-MCR03-IPC_B 6650,614 r180 top value=100kΩ
R153 "CRCW060320K0FKTA" FP-MCR03-IPC_B 6850,570 r180 top value=20kΩ
R154 "RC0603FR-07100KL" FP-MCR03-IPC_B 6650,546 r180 top value=100kΩ
R155 "RC0603JR-072M7L" FP-MCR03-IPC_B 6650,410 r0 top value=2.7MΩ
R156 "RC0603JR-072M7L" FP-MCR03-IPC_B 6650,342 r180 top value=2.7MΩ
R157 "TNPW1206249KBEEA" RESC3216X65X50NL15T25 7660,7150 r270 bottom value=249kΩ
R158 "TNPW1206249KBEEA" RESC3216X65X50NL15T25 7300,7150 r270 bottom value=249kΩ
R159 "TNPW1206249KBEEA" RESC3216X65X50NL15T25 6940,7150 r270 bottom value=249kΩ
R160 "TNPW1206249KBEEA" RESC3216X65X50NL15T25 6580,7150 r270 bottom value=249kΩ
R161 "TNPW1206249KBEEA" RESC3216X65X50NL15T25 7660,6960 r270 bottom value=249kΩ
R162 "TNPW1206249KBEEA" RESC3216X65X50NL15T25 7300,6960 r270 bottom value=249kΩ
R163 "TNPW1206249KBEEA" RESC3216X65X50NL15T25 6940,6960 r270 bottom value=249kΩ
R164 "TNPW1206249KBEEA" RESC3216X65X50NL15T25 6580,6960 r270 bottom value=249kΩ
R165 "TNPW1206249KBEEA" RESC3216X65X50NL15T25 7660,6770 r270 bottom value=249kΩ
R166 "TNPW1206249KBEEA" RESC3216X65X50NL15T25 7300,6770 r270 bottom value=249kΩ
R167 "TNPW1206249KBEEA" RESC3216X65X50NL15T25 6940,6770 r270 bottom value=249kΩ
R168 "TNPW1206249KBEEA" RESC3216X65X50NL15T25 6580,6770 r270 bottom value=249kΩ
R169 "TNPW1206249KBEEA" RESC3216X65X50NL15T25 7660,6580 r270 bottom value=249kΩ
R170 "TNPW1206249KBEEA" RESC3216X65X50NL15T25 7300,6580 r270 bottom value=249kΩ
R171 "TNPW1206249KBEEA" RESC3216X65X50NL15T25 6940,6580 r270 bottom value=249kΩ
R172 "TNPW1206249KBEEA" RESC3216X65X50NL15T25 6580,6580 r270 bottom value=249kΩ
R173 "TNPW1206249KBEEA" RESC3216X65X50NL15T25 7660,6390 r270 bottom value=249kΩ
R174 "TNPW1206249KBEEA" RESC3216X65X50NL15T25 7300,6390 r270 bottom value=249kΩ
R175 "TNPW1206249KBEEA" RESC3216X65X50NL15T25 6940,6390 r270 bottom value=249kΩ
R176 "TNPW1206249KBEEA" RESC3216X65X50NL15T25 6580,6390 r270 bottom value=249kΩ
R177 "TNPW1206249KBEEA" RESC3216X65X50NL15T25 7660,6200 r270 bottom value=249kΩ
R178 "TNPW1206249KBEEA" RESC3216X65X50NL15T25 7300,6200 r270 bottom value=249kΩ
R179 "TNPW1206249KBEEA" RESC3216X65X50NL15T25 6940,6200 r270 bottom value=249kΩ
R180 "TNPW1206249KBEEA" RESC3216X65X50NL15T25 6580,6200 r270 bottom value=249kΩ
R181 "ERJ-PB3B1801V" FP-MCR03-IPC_B 7772,6040 r90 bottom value=1.8kΩ
R182 "RC0603FR-074K99L" FP-MCR03-IPC_B 7548,6040 r270 bottom value=4.99kΩ
R183 "CRCW06030000Z0EB" FP-MCR03-IPC_B 7480,6040 r90 bottom value=0Ω
R184 "ERJ-PB3B1801V" FP-MCR03-IPC_B 7412,6040 r90 bottom value=1.8kΩ
R185 "RC0603FR-074K99L" FP-MCR03-IPC_B 7188,6040 r270 bottom value=4.99kΩ
R186 "CRCW06030000Z0EB" FP-MCR03-IPC_B 7120,6040 r90 bottom value=0Ω
R187 "ERJ-PB3B1801V" FP-MCR03-IPC_B 7052,6040 r90 bottom value=1.8kΩ
R188 "RC0603FR-074K99L" FP-MCR03-IPC_B 6828,6040 r270 bottom value=4.99kΩ
R189 "CRCW06030000Z0EB" FP-MCR03-IPC_B 6760,6040 r90 bottom value=0Ω
R190 "ERJ-PB3B3741V" FP-MCR03-IPC_B 6692,6040 r270 bottom value=3.74kΩ
R191 "RC0603FR-074K99L" FP-MCR03-IPC_B 6468,6040 r270 bottom value=4.99kΩ
R192 "CRCW06030000Z0EB" FP-MCR03-IPC_B 7805,5258 r0 bottom value=0Ω
R193 "RC0603JR-07120RL" FP-MCR03-IPC_B 7805,5190 r180 bottom value=120Ω
R194 "RC0603JR-07120RL" FP-MCR03-IPC_B 7805,5122 r180 bottom value=120Ω
R195 "RC0603JR-07120RL" FP-MCR03-IPC_B 7805,5054 r0 bottom value=120Ω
